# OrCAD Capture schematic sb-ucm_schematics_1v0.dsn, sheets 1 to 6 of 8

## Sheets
1 07. Ethernet, Camera & Headers: size C; title: SB-UCM    07. Ethernet, Camera & Headers; rev: 1.0; note: 8000076000; note: 17 HaYetsira Street; note: Yokneam Illit, Israel 2069208
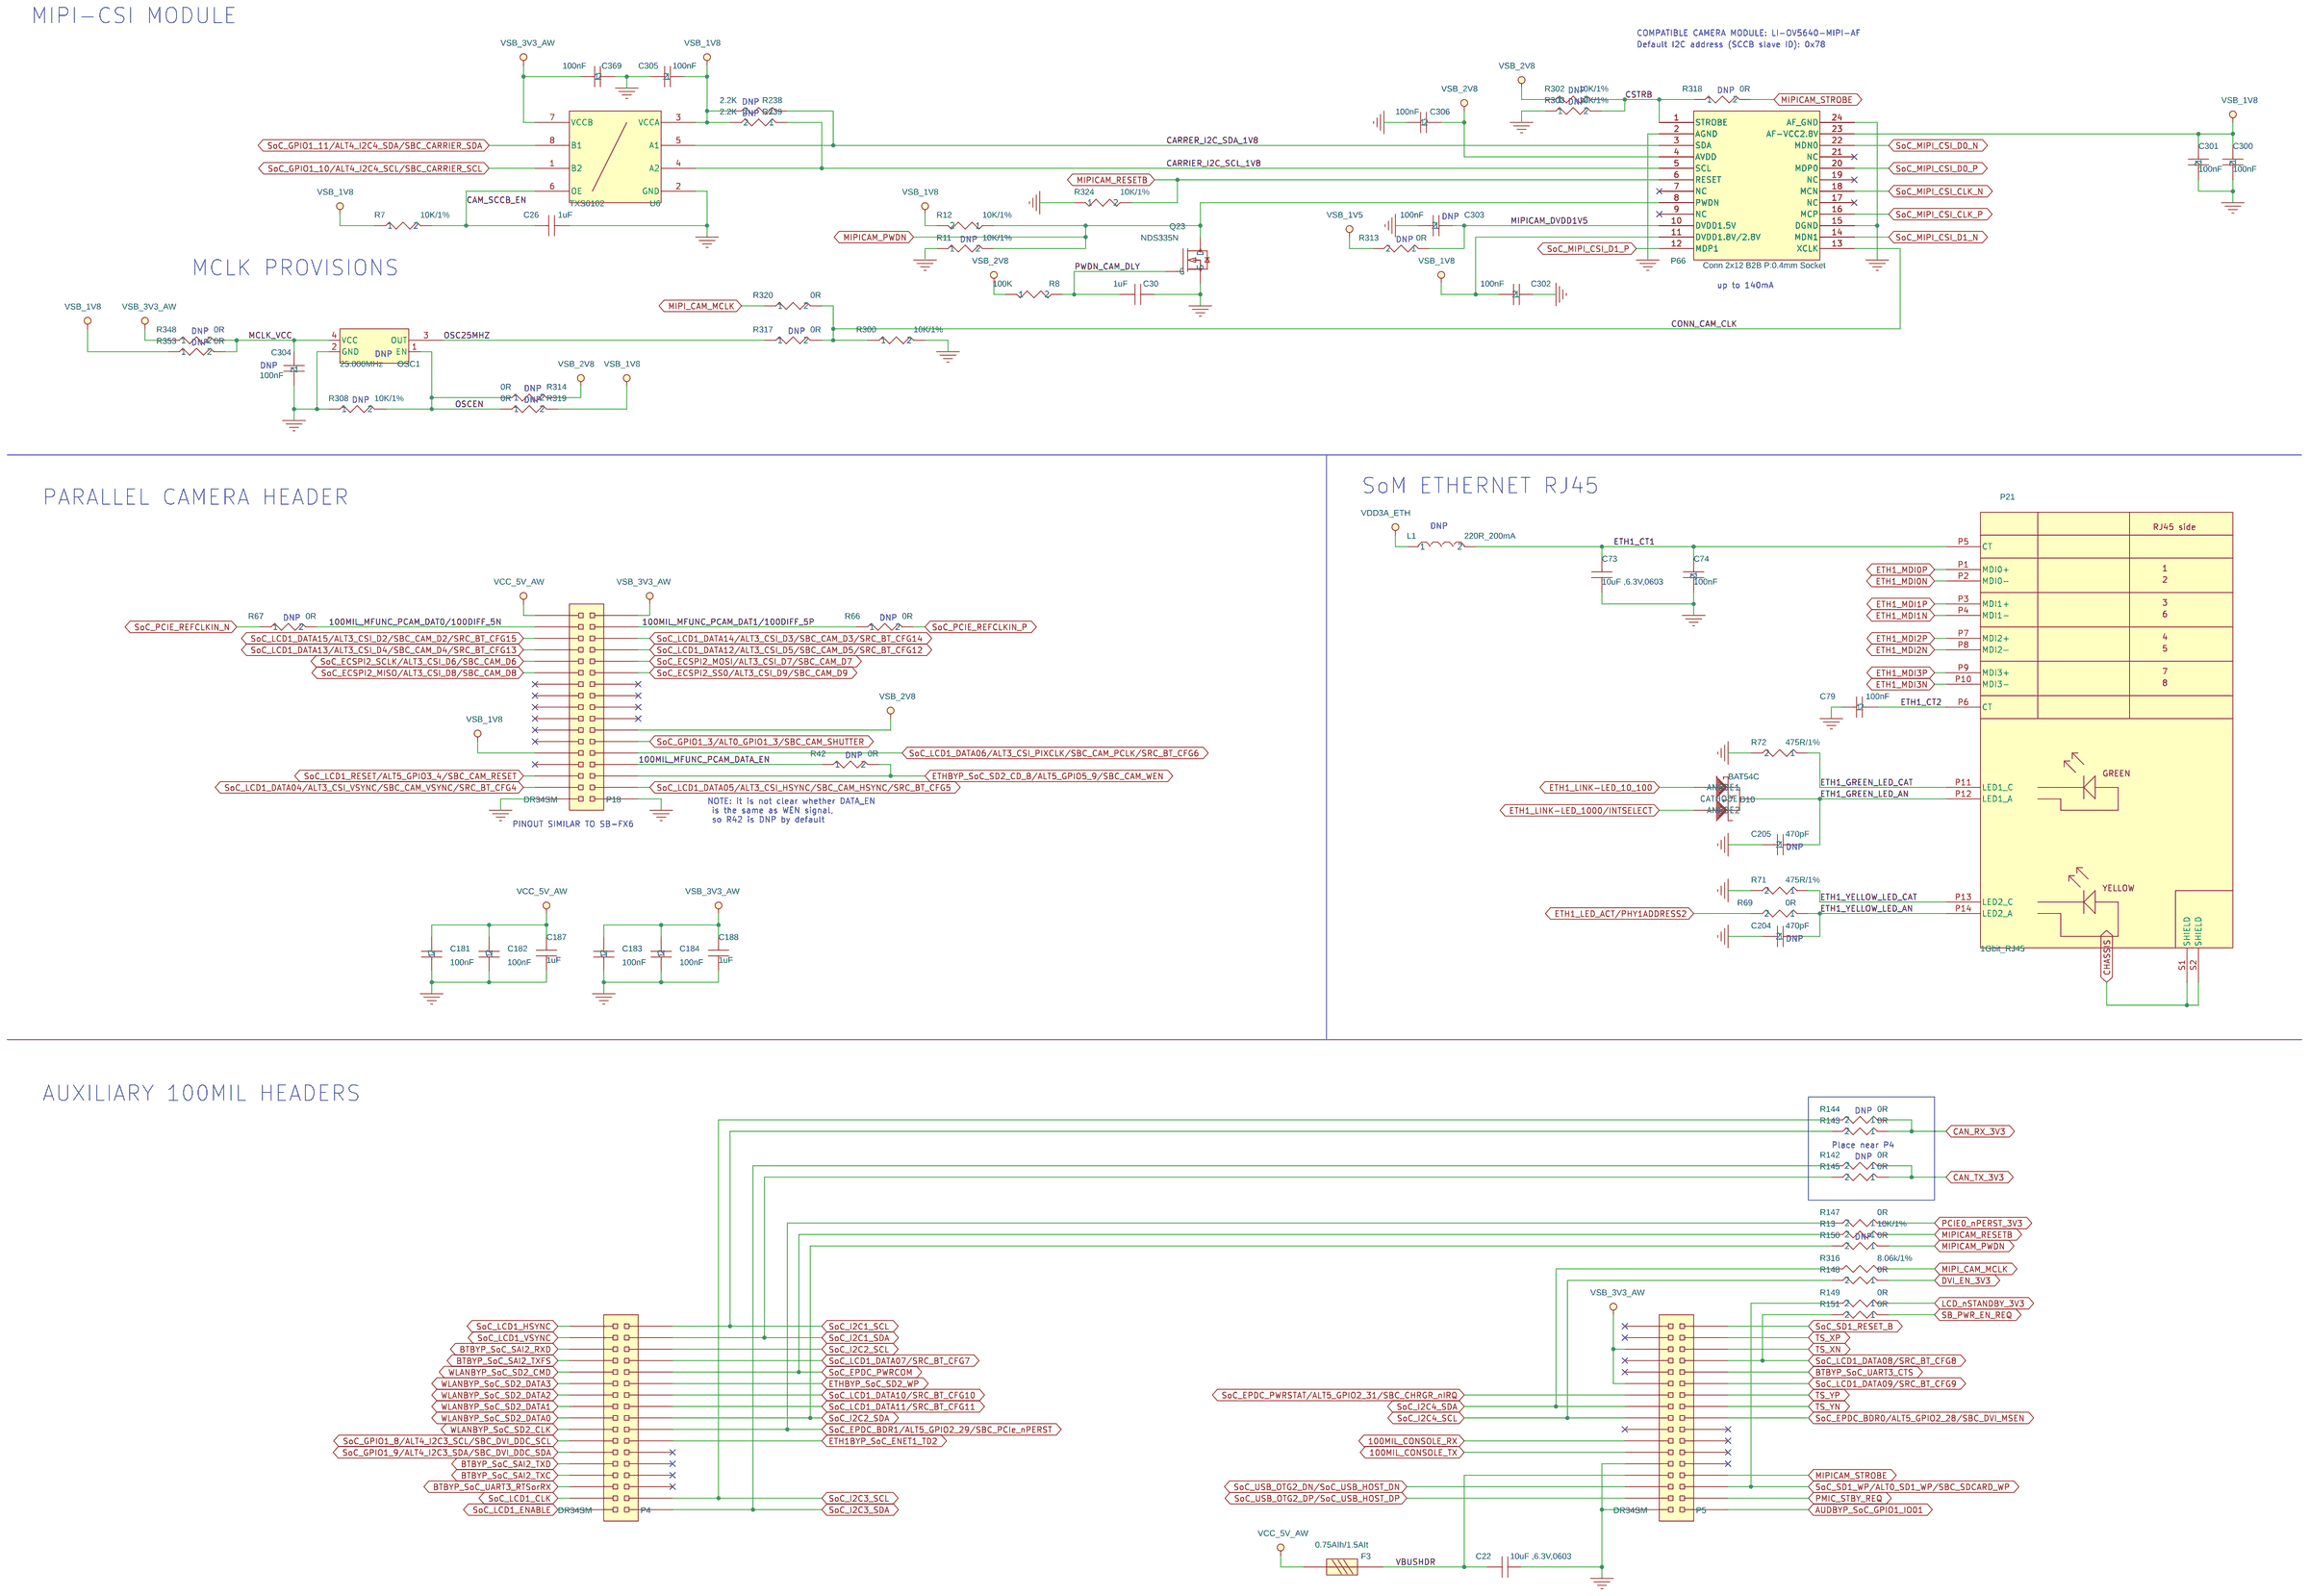
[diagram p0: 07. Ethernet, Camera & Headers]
2 02. Board Revision History: title: SB-UCM    02. Board Revision History
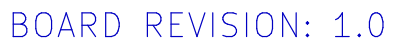
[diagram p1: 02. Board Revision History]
3 01. Index: size C; title: SB-UCM    01. Index
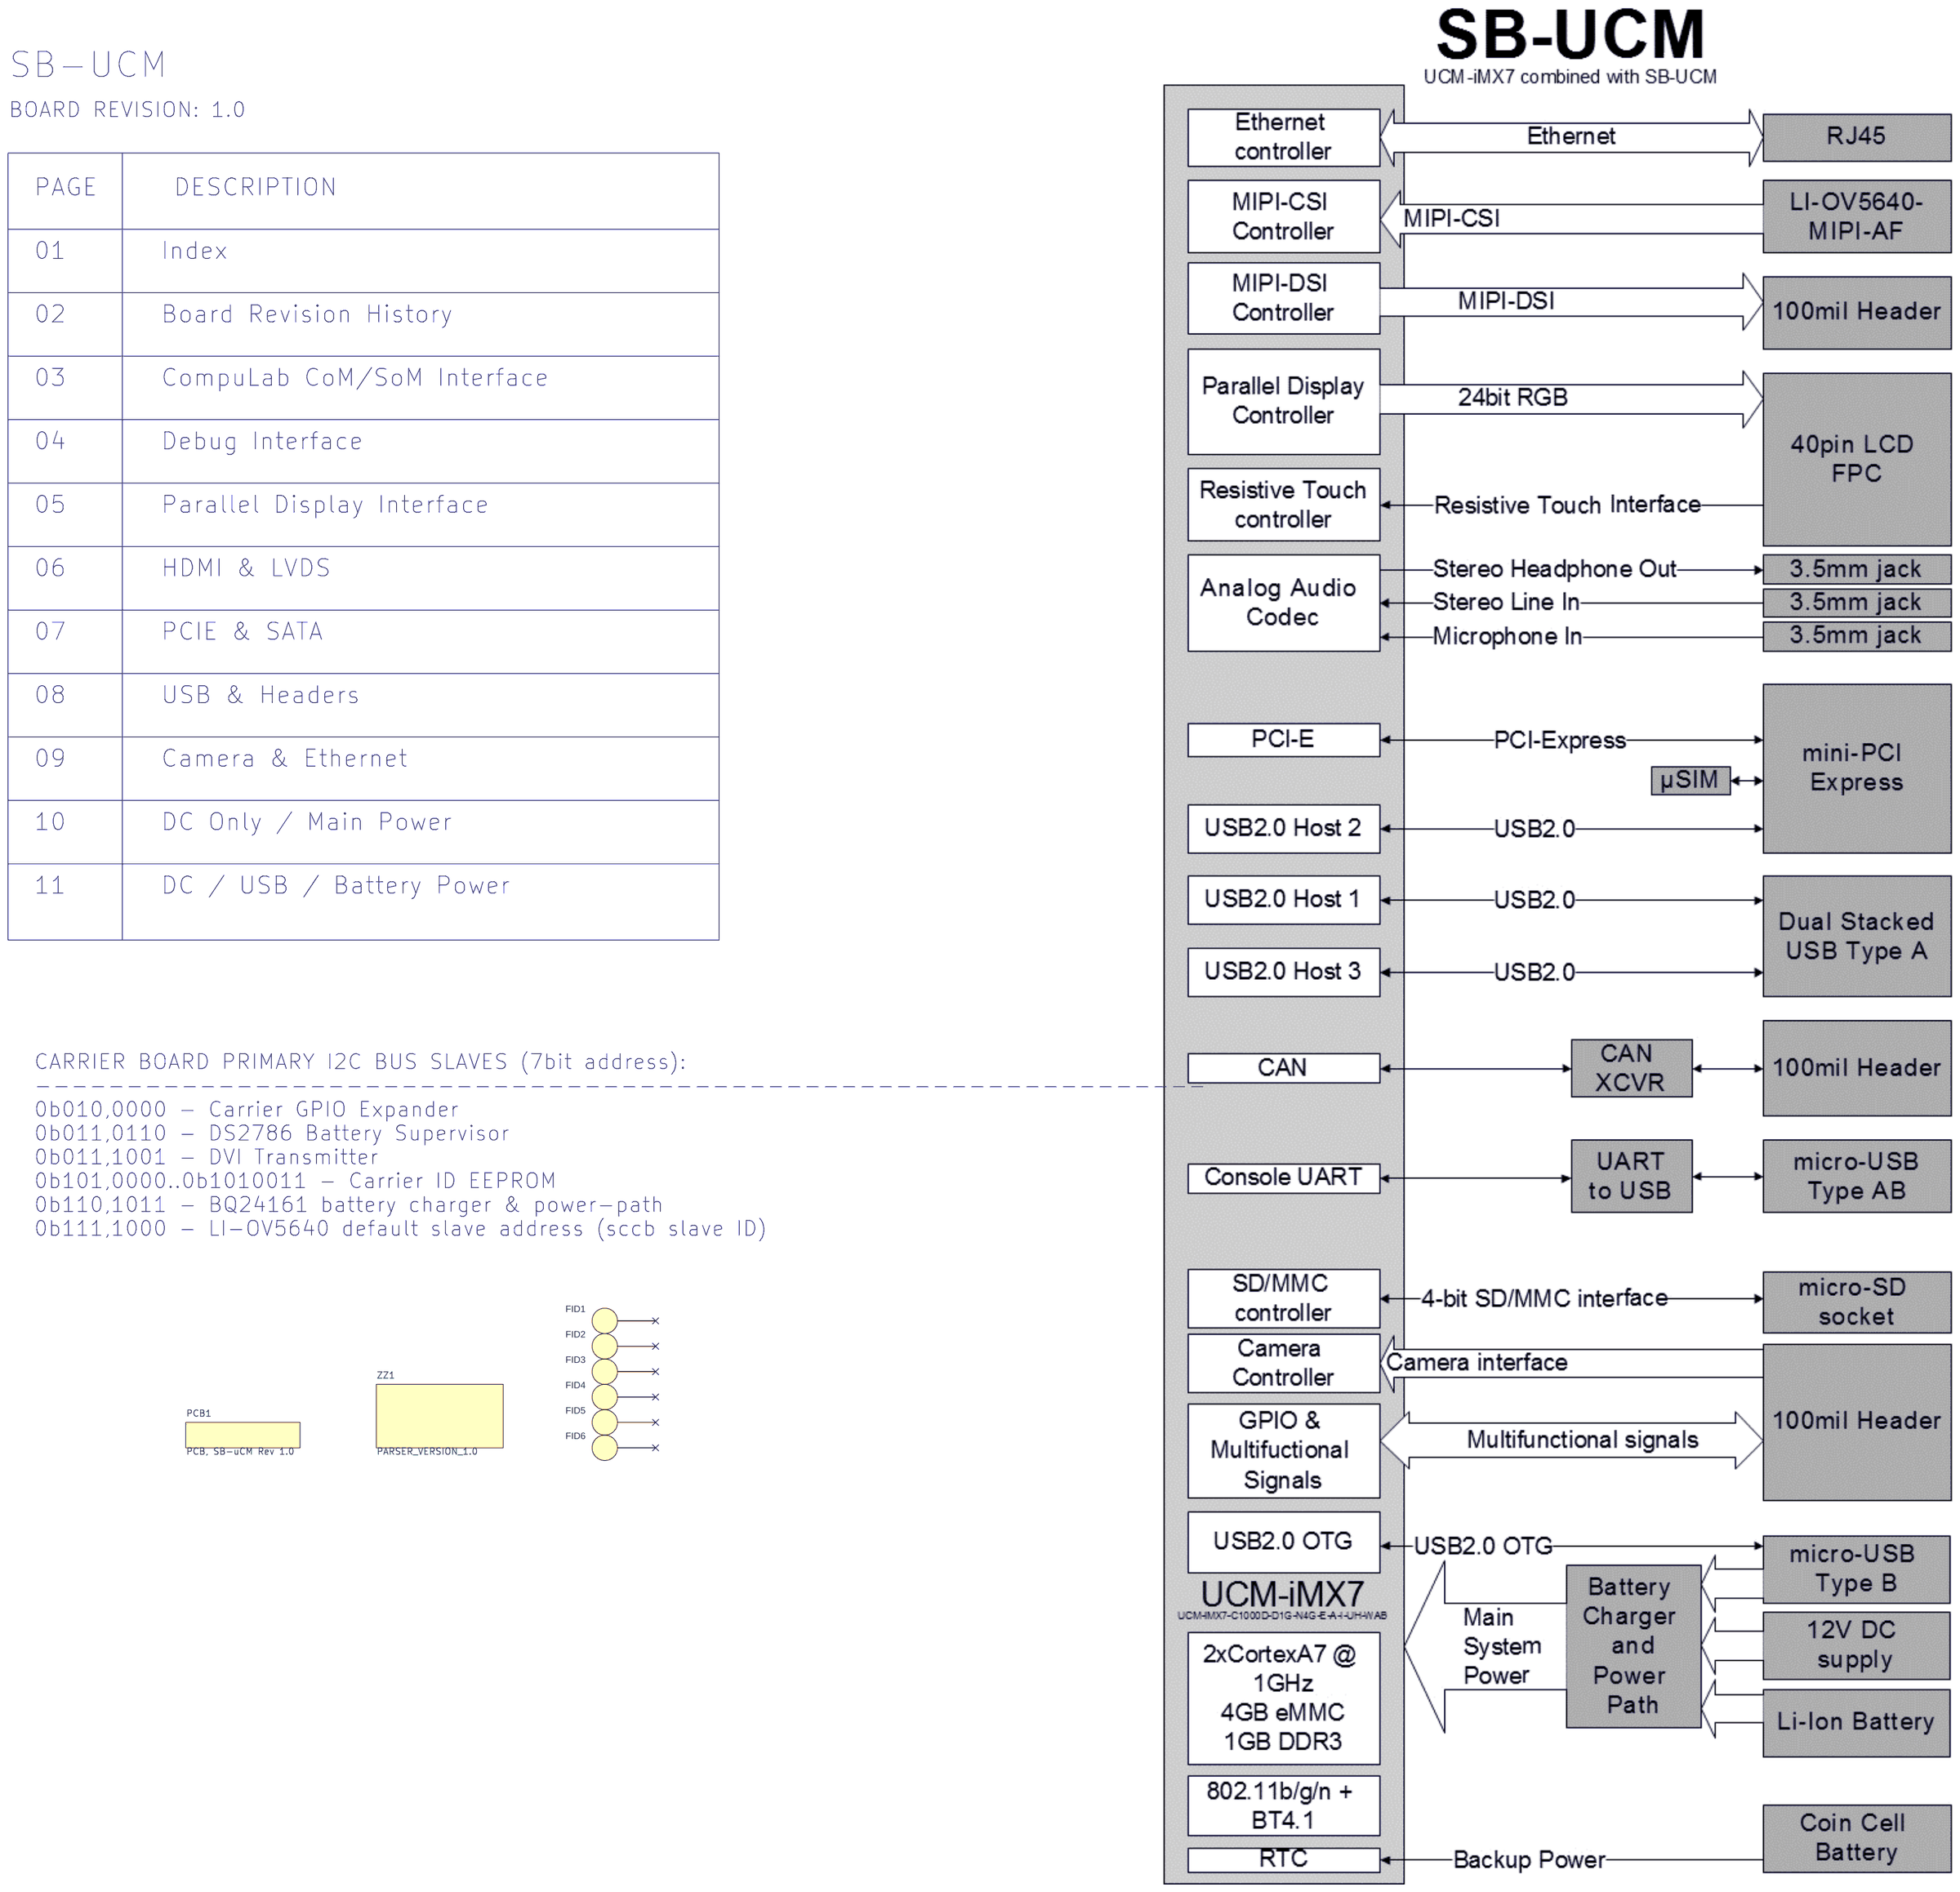
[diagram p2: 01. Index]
4 04. Console, CAN, SD, Buttons: size C; title: SB-UCM    04. Console, CAN, SD, Buttons
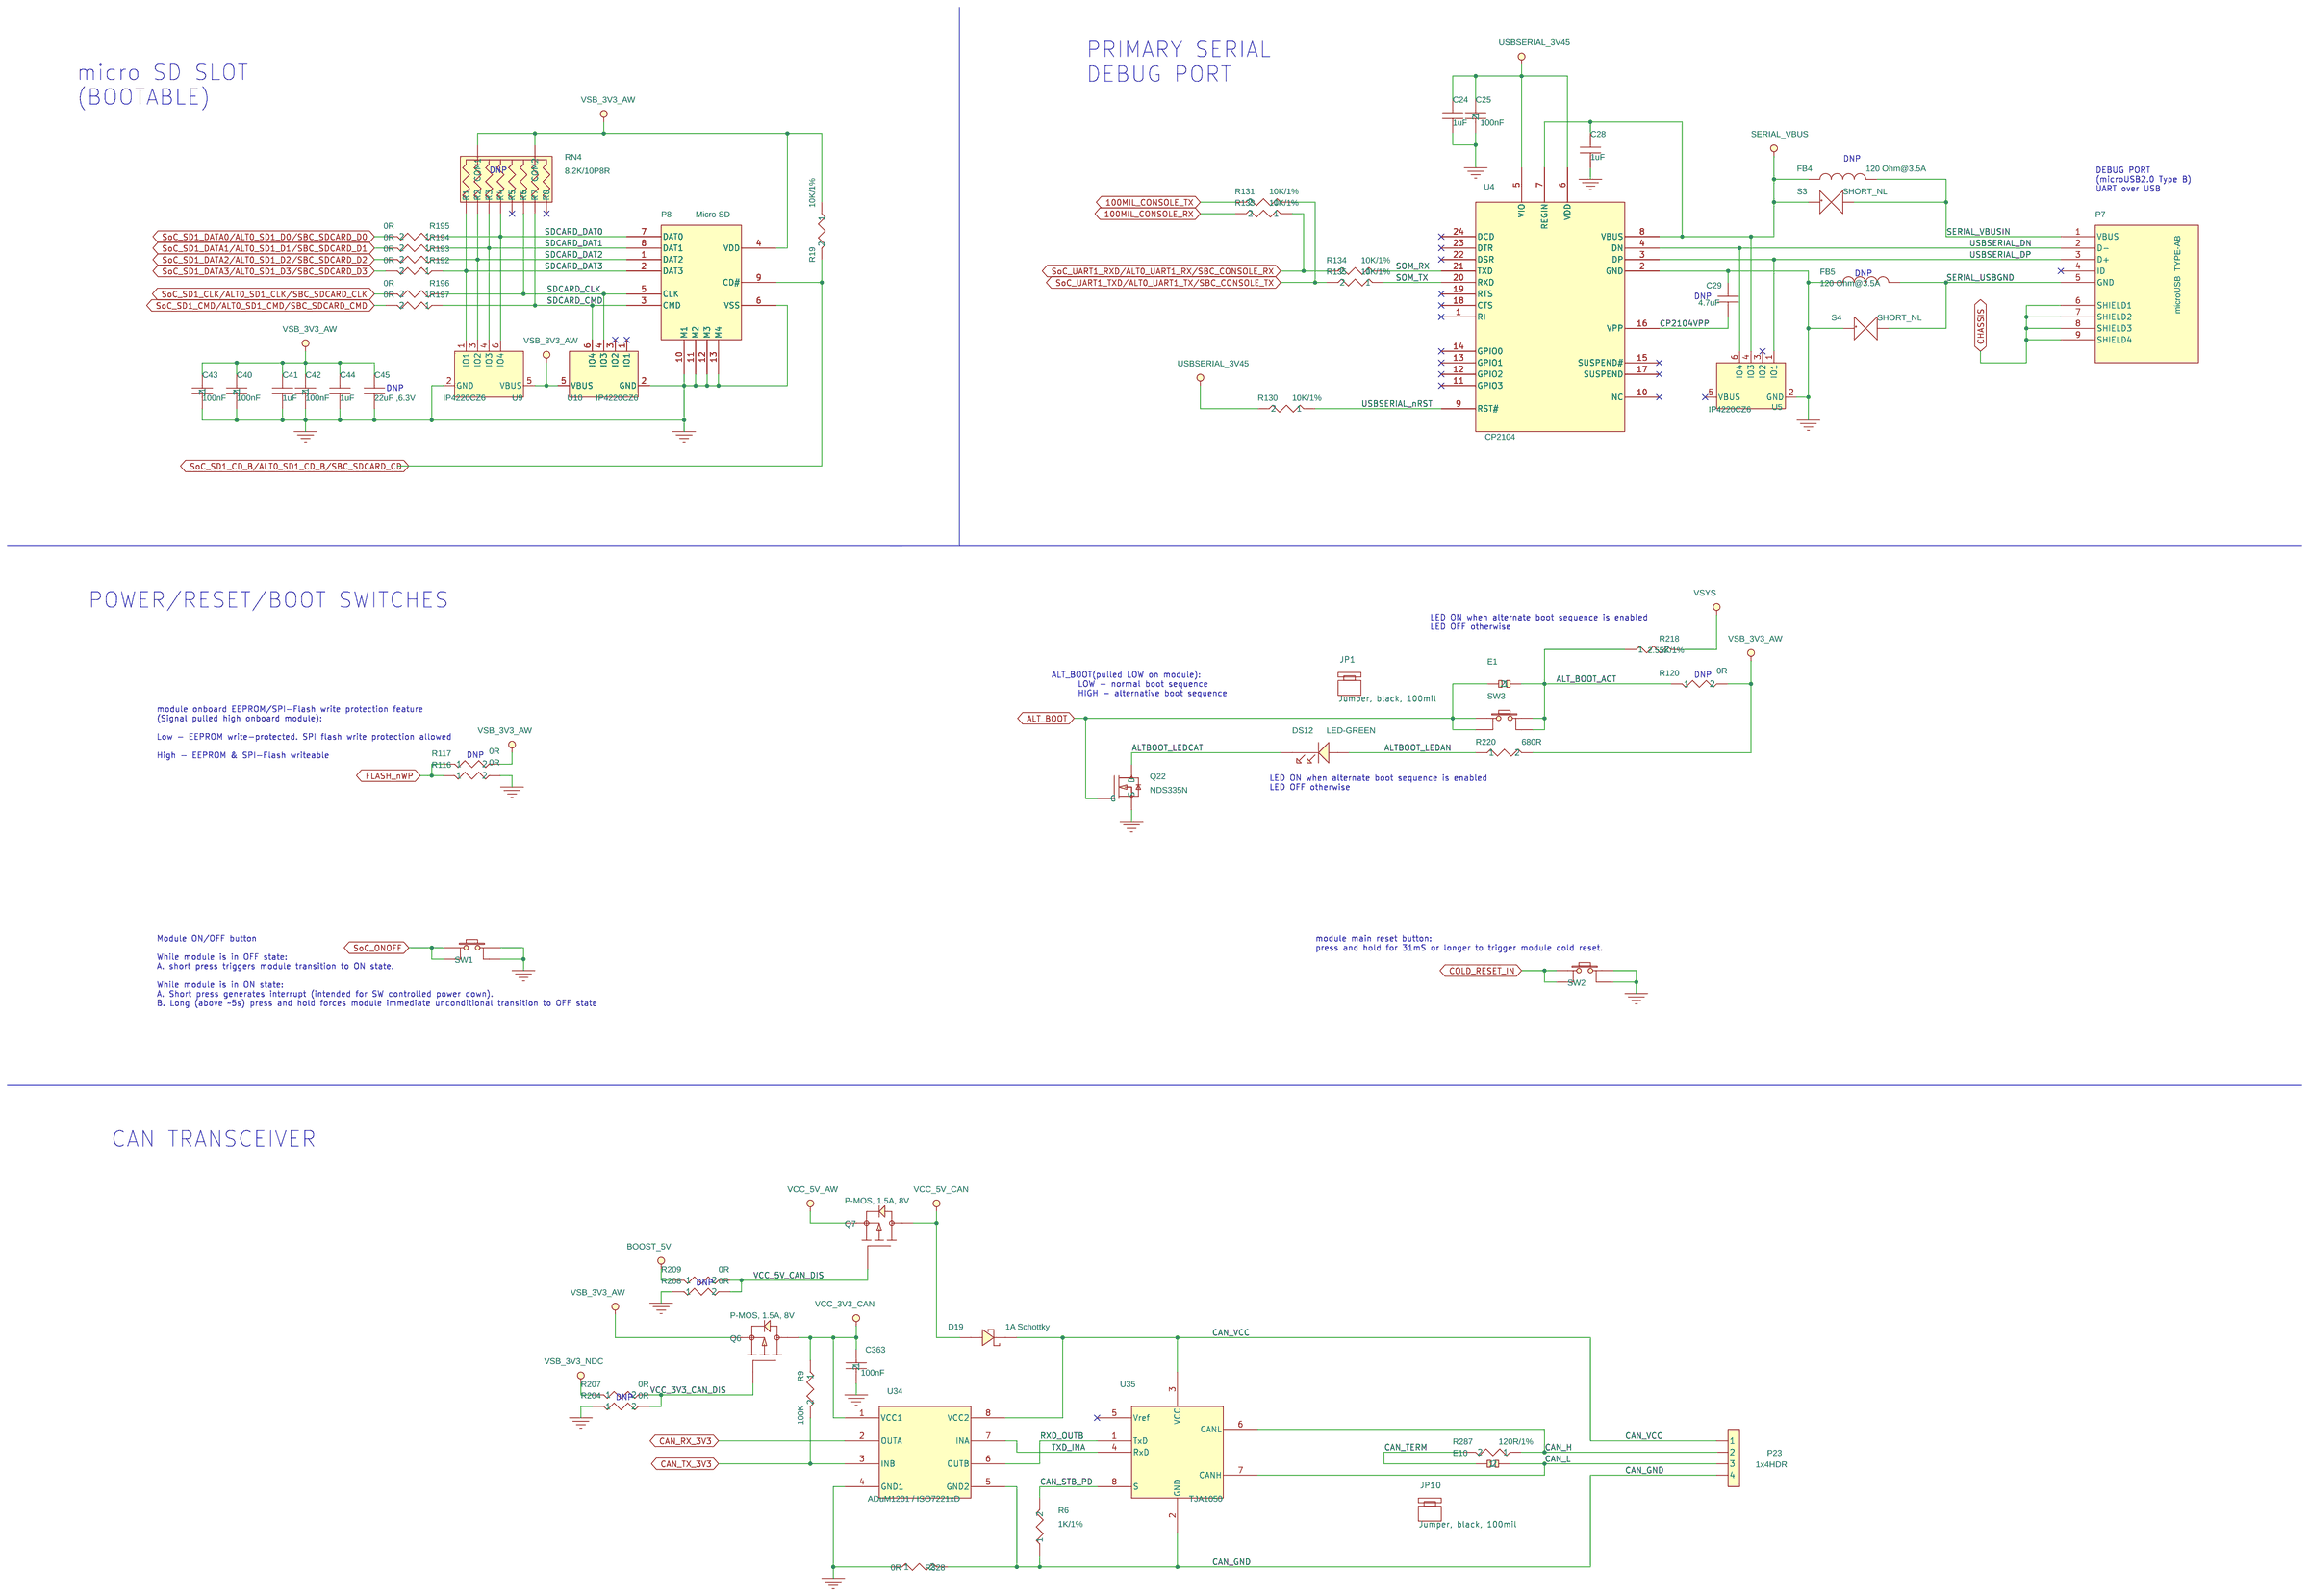
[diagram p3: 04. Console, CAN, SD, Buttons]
5 05. Display: size C; title: SB-UCM    05. Display
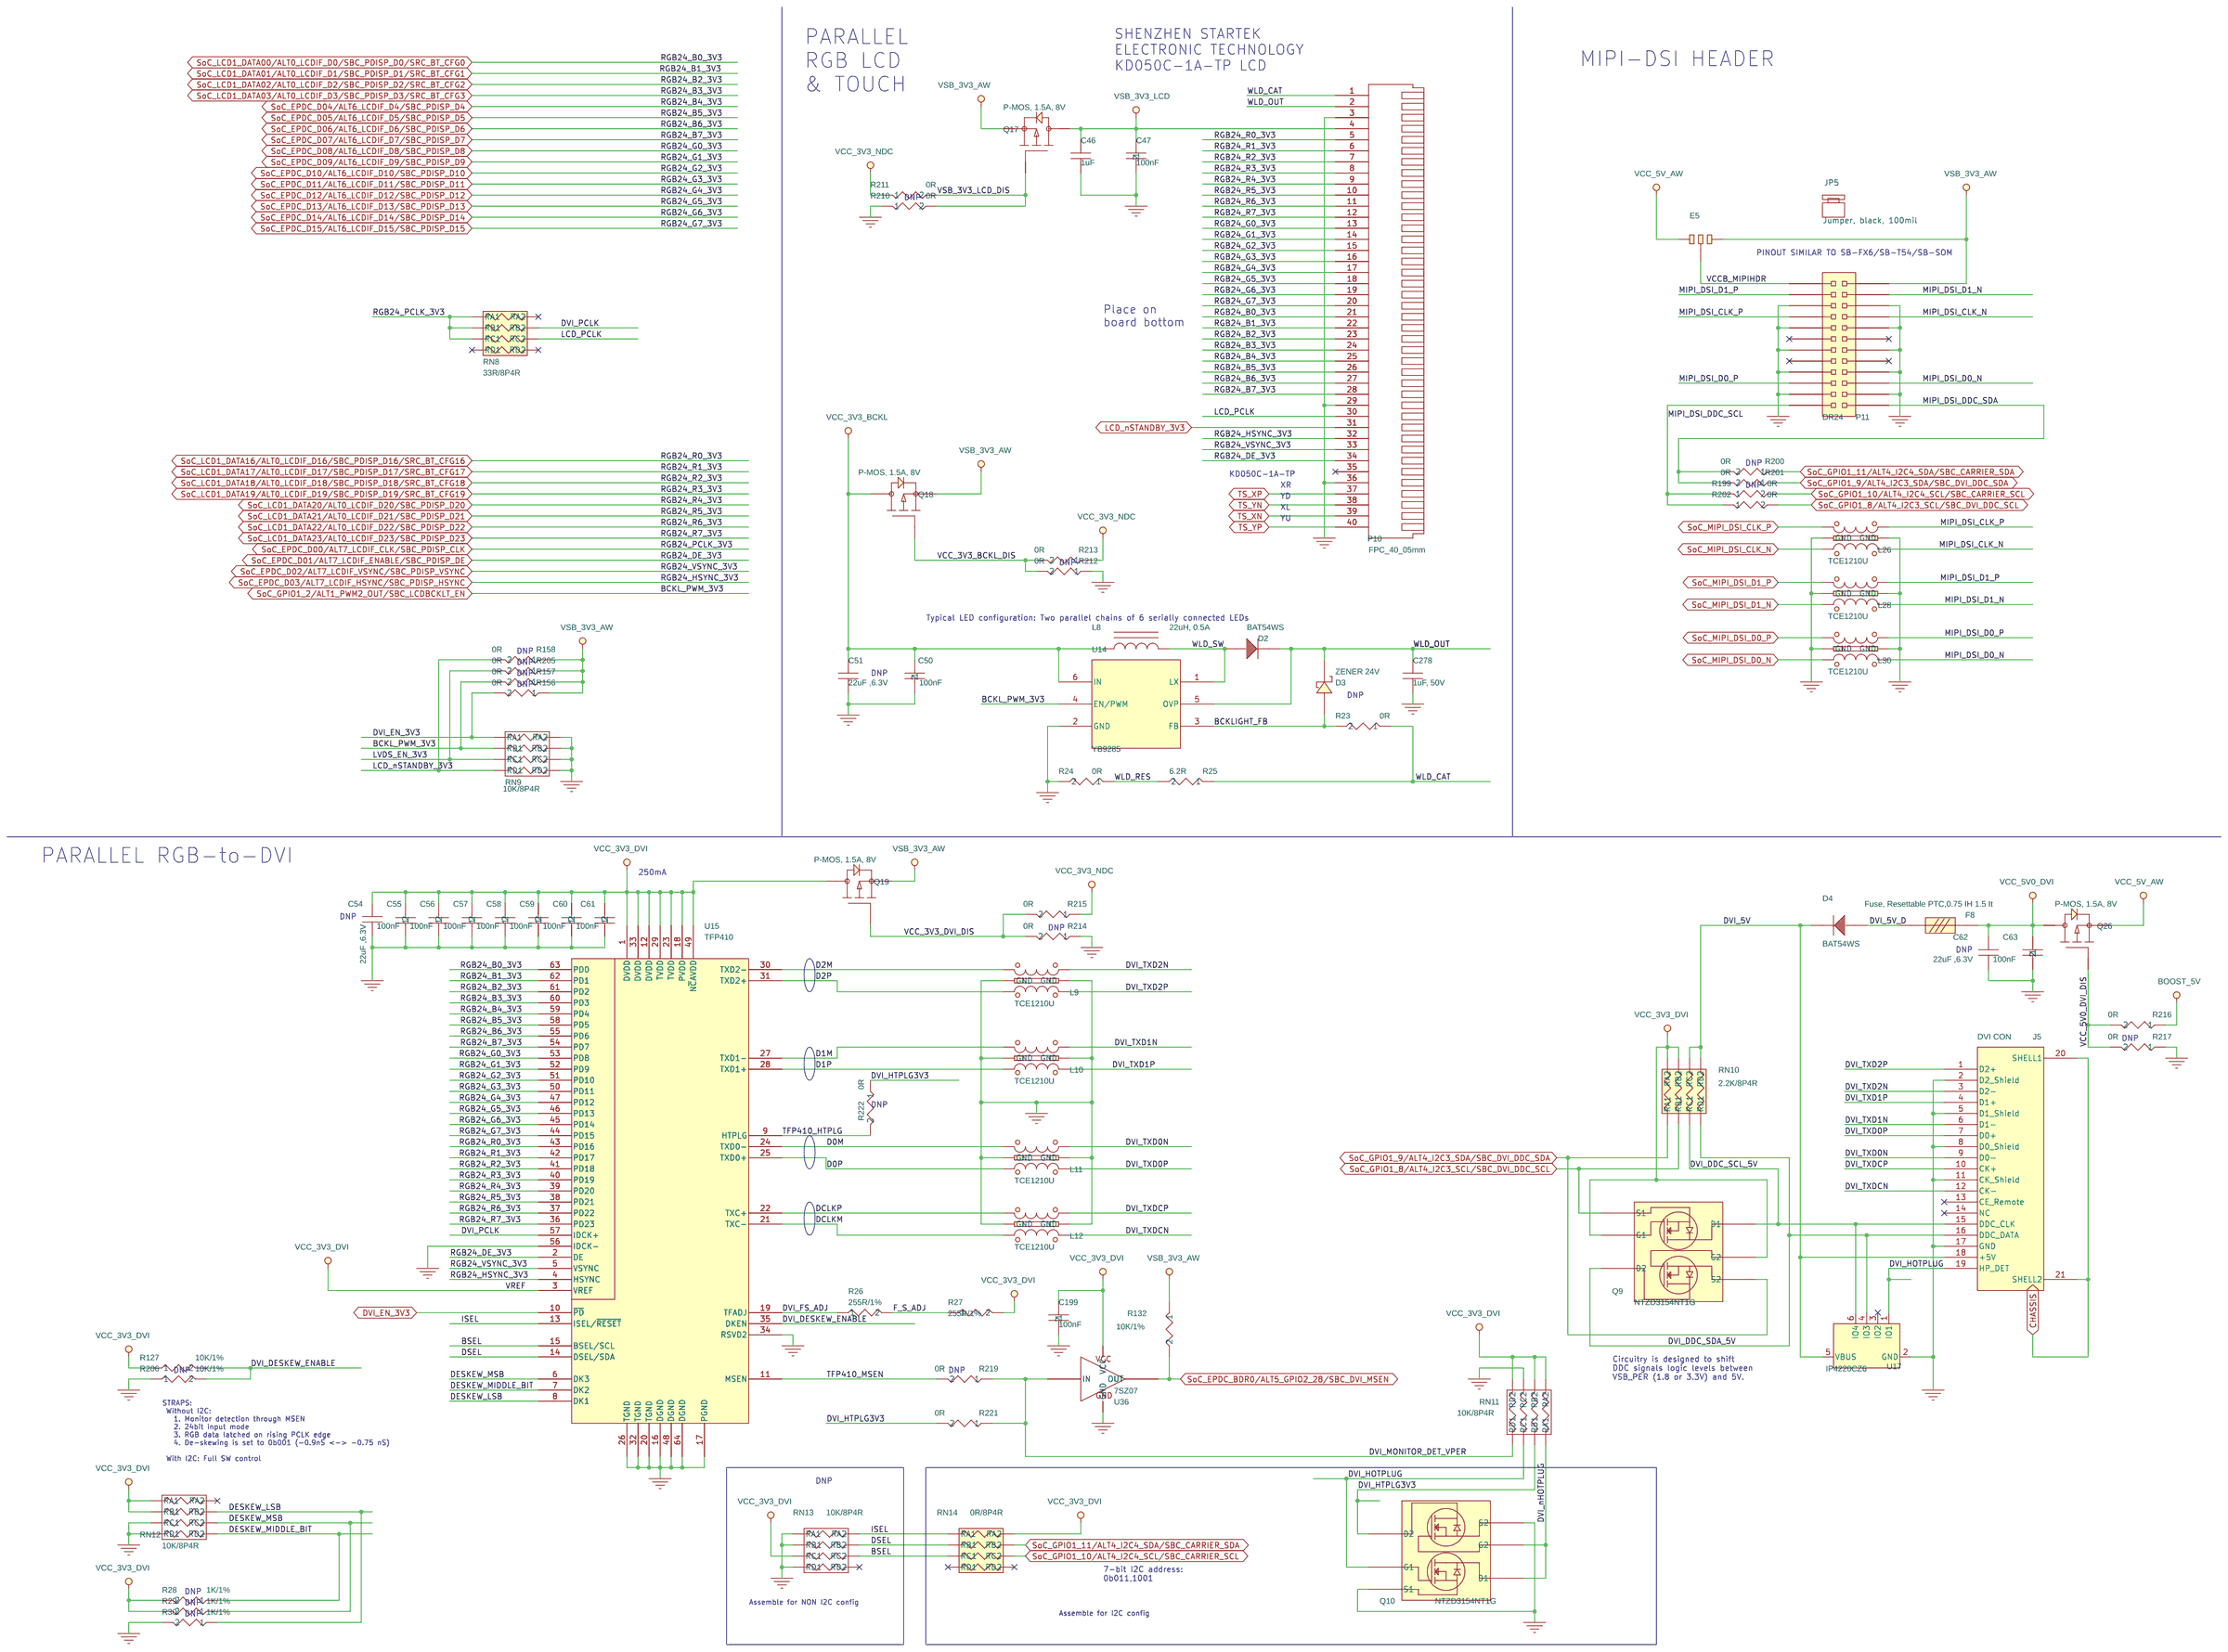
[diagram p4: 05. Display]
6 06. PCIE, USB & Misc.: size C; title: SB-UCM    06. PCIE, USB & Misc.
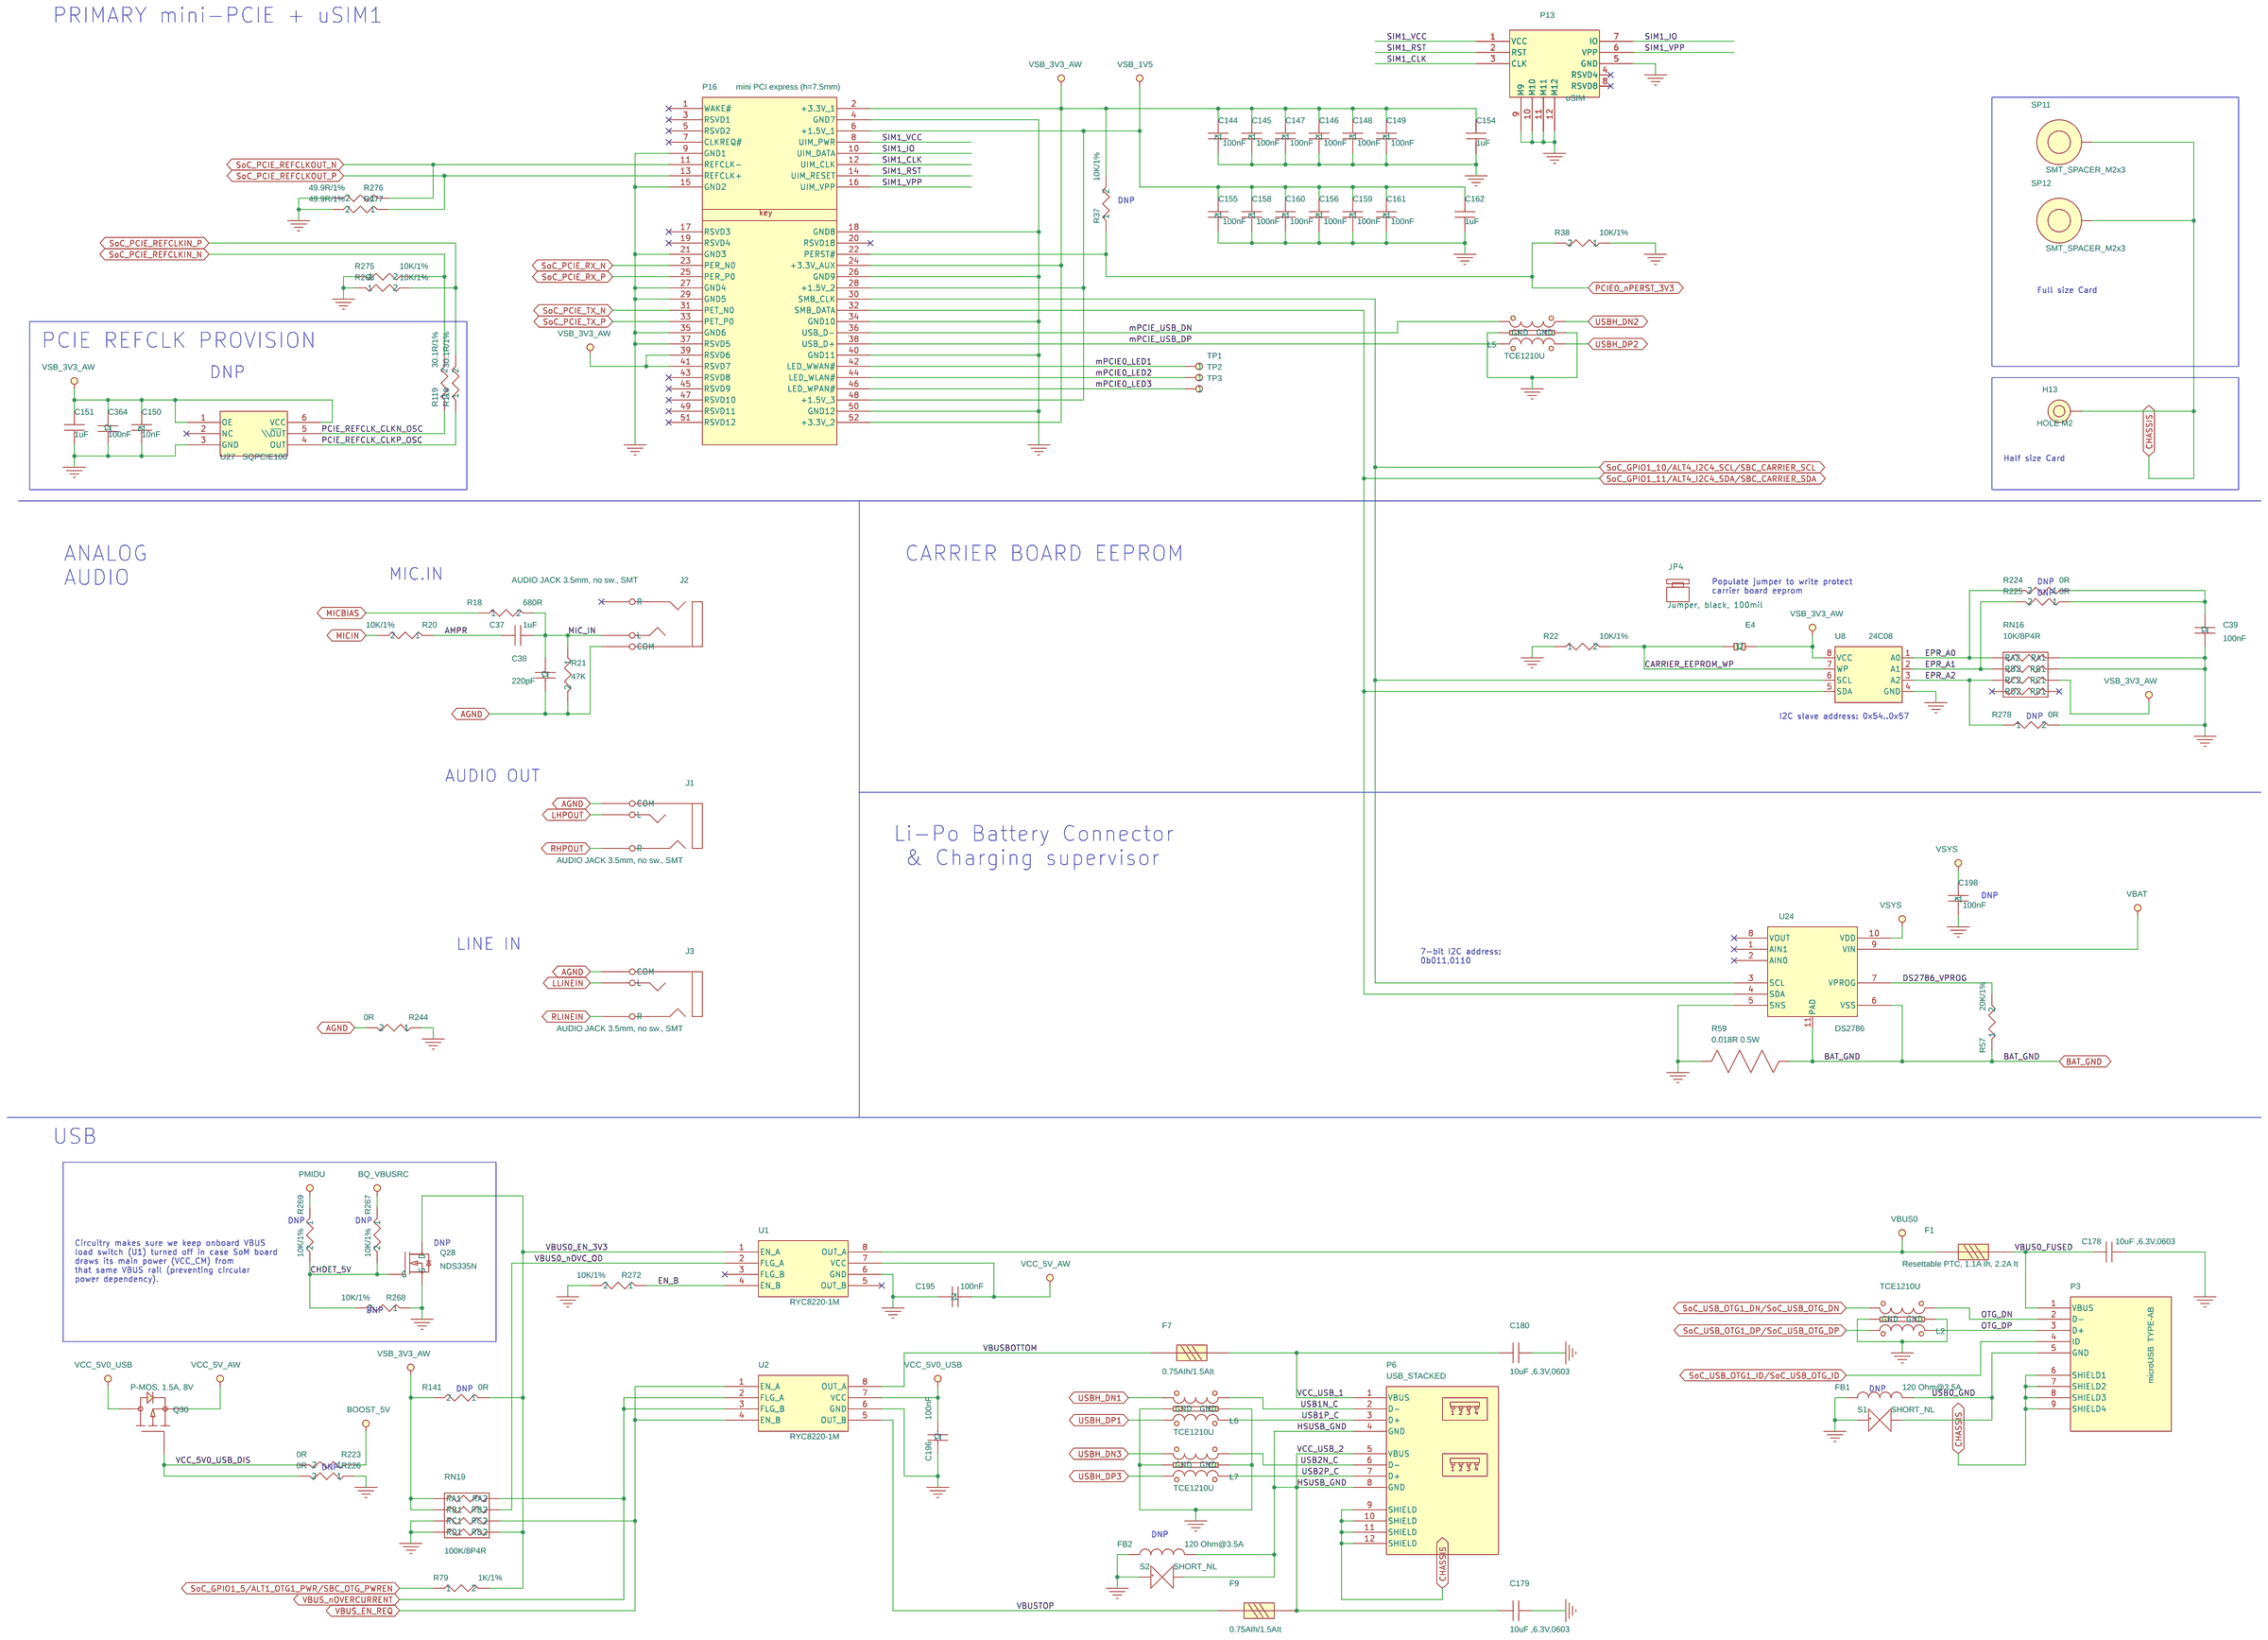
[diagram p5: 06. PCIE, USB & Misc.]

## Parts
sheet 01. Index
FID1  FIDUCIAL  [FIDUCIAL]
FID2  FIDUCIAL  [FIDUCIAL]
FID3  FIDUCIAL  [FIDUCIAL]
FID4  FIDUCIAL  [FIDUCIAL]
FID5  FIDUCIAL  [FIDUCIAL]
FID6  FIDUCIAL  [FIDUCIAL]
PCB1  PCB, SB-uCM Rev 1.0  [PCB]
ZZ1  PARSER_VERSION_1.0  [PCB]
sheet 04. Console, CAN, SD, Buttons
C24  1uF  [RC0402]
C25  100nF  [RC0402]
C28  1uF  [RC0402]
C29  4.7uF  [C0603-08]
C40  100nF  [RC0402]
C41  1uF  [RC0402]
C42  100nF  [RC0402]
C43  100nF  [RC0402]
C44  1uF  [RC0402]
C45  22uF ,6.3V  [RC0603]
C363  100nF  [RC0402]
D19  1A Schottky  [SOD-123]
DS12  LED-GREEN  [LED-1206]
E1  HDR1X2  [1X2THHDR]
E10  HDR1X2  [1X2THHDR]
FB4  120 Ohm@3.5A  [FB1206]
FB5  120 Ohm@3.5A  [FB1206]
JP1  Jumper, black, 100mil  [Shunt/Jumper]
JP10  Jumper, black, 100mil  [Shunt/Jumper]
P7  microUSB  TYPE-AB  [MICRO-USB-AB-RA-SM]
P8  Micro SD  [MicroSD-PP-RA-CD-SM]
P23  1x4HDR  [1X4THHDR]
Q6  P-MOS, 1.5A, 8V  [SOT23]
Q7  P-MOS, 1.5A, 8V  [SOT23]
Q22  NDS335N  [SOT23]
R6  1K/1%  [RC0402]
R9  100K  [RC0402]
R19  10K/1%  [RC0402]
R116  0R  [RC0402]
R117  0R  [RC0402]
R120  0R  [RC0402]
R130  10K/1%  [RC0402]
R131  10K/1%  [RC0402]
R133  10K/1%  [RC0402]
R134  10K/1%  [RC0402]
R135  10K/1%  [RC0402]
R192  0R  [RC0402]
R193  0R  [RC0402]
R194  0R  [RC0402]
R195  0R  [RC0402]
R196  0R  [RC0402]
R197  0R  [RC0402]
R204  0R  [RC0402]
R207  0R  [RC0402]
R208  0R  [RC0402]
R209  0R  [RC0402]
R218  2.55K/1%  [RC0402]
R220  680R  [RC0402]
R287  120R/1%  [RC0603]
R328  0R  [RC0402]
RN4  8.2K/10P8R  [RESNET10P1206]
S3  SHORT_NL  [JUMPER-VIA_1]
S4  SHORT_NL  [JUMPER-VIA_1]
SW1  PushB  [TACTSW6x6SM]
SW2  PushB  [TACTSW6x6SM]
SW3  PushB  [TACTSW6x6SM]
U4  CP2104  [MO-220VGGD-8]
U5  IP4220CZ6  [SOT23-6L-H1]
U9  IP4220CZ6  [SOT23-6L-H1]
U10  IP4220CZ6  [SOT23-6L-H1]
U34  ADuM1201 / ISO7221xD  [SO-8-150]
U35  TJA1050  [SO-8-150]
sheet 05. Display
C46  1uF  [RC0402]
C47  100nF  [RC0402]
C50  100nF  [RC0402]
C51  22uF ,6.3V  [RC0603]
C54  22uF ,6.3V  [RC0603]
C55  100nF  [RC0402]
C56  100nF  [RC0402]
C57  100nF  [RC0402]
C58  100nF  [RC0402]
C59  100nF  [RC0402]
C60  100nF  [RC0402]
C61  100nF  [RC0402]
C62  22uF ,6.3V  [RC0603]
C63  100nF  [RC0402]
C199  100nF  [RC0402]
C278  1uF, 50V  [RC0603]
D2  BAT54WS  [SOD-323]
D3  ZENER 24V  [SOD-123]
D4  BAT54WS  [SOD-323]
E5  JP3  [1X3THHDR]
F8  Fuse, Resettable PTC,0.75 IH 1.5 It  [FUSE-1206]
J5  DVI CON  [HDMI-A19-RASM]
JP5  Jumper, black, 100mil  [Shunt/Jumper]
L8  22uH, 0.5A  [IND4x4_5x3_2S]
L9  TCE1210U  [EMI1012-ESD]
L10  TCE1210U  [EMI1012-ESD]
L11  TCE1210U  [EMI1012-ESD]
L12  TCE1210U  [EMI1012-ESD]
L26  TCE1210U  [EMI1012-ESD]
L28  TCE1210U  [EMI1012-ESD]
L30  TCE1210U  [EMI1012-ESD]
P10  FPC_40_05mm  [FPC05SM40-1]
P11  DR24  [2X12THHDR]
Q9  NTZD3154NT1G  [SOT-563-6]
Q10  NTZD3154NT1G  [SOT-563-6]
Q17  P-MOS, 1.5A, 8V  [SOT23]
Q18  P-MOS, 1.5A, 8V  [SOT23]
Q19  P-MOS, 1.5A, 8V  [SOT23]
Q26  P-MOS, 1.5A, 8V  [SOT23]
R23  0R  [RC0402]
R24  0R  [RC0402]
R25  6.2R  [RC0402]
R26  255R/1%  [RC0402]
R27  255R/1%  [RC0402]
R28  1K/1%  [RC0402]
R29  1K/1%  [RC0402]
R30  1K/1%  [RC0402]
R127  10K/1%  [RC0402]
R132  10K/1%  [RC0402]
R156  0R  [RC0402]
R157  0R  [RC0402]
R158  0R  [RC0402]
R199  0R  [RC0402]
R200  0R  [RC0402]
R201  0R  [RC0402]
R202  0R  [RC0402]
R205  0R  [RC0402]
R206  10K/1%  [RC0402]
R210  0R  [RC0402]
R211  0R  [RC0402]
R212  0R  [RC0402]
R213  0R  [RC0402]
R214  0R  [RC0402]
R215  0R  [RC0402]
R216  0R  [RC0402]
R217  0R  [RC0402]
R219  0R  [RC0402]
R221  0R  [RC0402]
R222  0R  [RC0402]
RN8  33R/8P4R  [RESNET8P0805]
RN9  10K/8P4R  [RESNET8P0805]
RN10  2.2K/8P4R  [RESNET8P0805]
RN11  10K/8P4R  [RESNET8P0805]
RN12  10K/8P4R  [RESNET8P0805]
RN13  10K/8P4R  [RESNET8P0805]
RN14  0R/8P4R  [RESNET8P0805]
U14  YB9285  [SOT23-6L]
U15  TFP410  [TQFP-64]
U17  IP4220CZ6  [SOT23-6L-H1]
U36  7SZ07  [SC70]
sheet 06. PCIE, USB & Misc.
C37  1uF  [RC0402]
C38  220pF  [RC0603]
C39  100nF  [RC0402]
C144  100nF  [RC0402]
C145  100nF  [RC0402]
C146  100nF  [RC0402]
C147  100nF  [RC0402]
C148  100nF  [RC0402]
C149  100nF  [RC0402]
C150  10nF  [RC0402]
C151  1uF  [RC0402]
C154  1uF  [RC0402]
C155  100nF  [RC0402]
C156  100nF  [RC0402]
C158  100nF  [RC0402]
C159  100nF  [RC0402]
C160  100nF  [RC0402]
C161  100nF  [RC0402]
C162  1uF  [RC0402]
C178  10uF ,6.3V,0603  [C0603-08]
C179  10uF ,6.3V,0603  [C0603-08]
C180  10uF ,6.3V,0603  [C0603-08]
C195  100nF  [RC0402]
C196  100nF  [RC0402]
C198  100nF  [RC0402]
C364  100nF  [RC0402]
E4  HDR1X2  [1X2THHDR]
F1  Resettable PTC, 1.1A Ih, 2.2A It  [FUSE-1206]
F7  0.75AIh/1.5AIt  [FUSE-1206]
F9  0.75AIh/1.5AIt  [FUSE-1206]
FB1  120 Ohm@3.5A  [FB1206]
FB2  120 Ohm@3.5A  [FB1206]
H13  HOLE M2  [M2PAD]
J1  AUDIO JACK 3.5mm, no sw., SMT  [AJ35-3P-SM]
J2  AUDIO JACK 3.5mm, no sw., SMT  [AJ35-3P-SM]
J3  AUDIO JACK 3.5mm, no sw., SMT  [AJ35-3P-SM]
JP4  Jumper, black, 100mil  [Shunt/Jumper]
L2  TCE1210U  [EMI1012-ESD]
L5  TCE1210U  [EMI1012-ESD]
L6  TCE1210U  [EMI1012-ESD]
L7  TCE1210U  [EMI1012-ESD]
P3  microUSB  TYPE-AB  [MICRO-USB-AB-RA-SM]
P6  USB_STACKED  [USB-2XA-TH]
P13  uSIM  [SKT-MicroSIM6-SM]
P16  mini PCI express (h=7.5mm)  [MINIPCIE-4]
Q28  NDS335N  [SOT23]
Q30  P-MOS, 1.5A, 8V  [SOT23]
R18  680R  [RC0402]
R20  10K/1%  [RC0402]
R21  47K  [RC0402]
R22  10K/1%  [RC0402]
R37  10K/1%  [RC0402]
R38  10K/1%  [RC0402]
R57  20K/1%  [RC0402]
R59  0.018R 0.5W  [R2010]
R79  1K/1%  [RC0402]
R118  30.1R/1%  [RC0402]
R119  30.1R/1%  [RC0402]
R141  0R  [RC0402]
R223  0R  [RC0402]
R224  0R  [RC0402]
R225  0R  [RC0402]
R226  0R  [RC0402]
R244  0R  [RC0402]
R265  10K/1%  [RC0402]
R267  10K/1%  [RC0402]
R268  10K/1%  [RC0402]
R269  10K/1%  [RC0402]
R272  10K/1%  [RC0402]
R275  10K/1%  [RC0402]
R276  49.9R/1%  [RC0402]
R277  49.9R/1%  [RC0402]
R278  0R  [RC0402]
RN16  10K/8P4R  [RESNET8P0805]
RN19  100K/8P4R  [RESNET8P0805]
S1  SHORT_NL  [JUMPER-VIA_1]
S2  SHORT_NL  [JUMPER-VIA_1]
SP11  SMT_SPACER_M2x3  [SpacerM2H4SM]
SP12  SMT_SPACER_M2x3  [SpacerM2H4SM]
TP1  TESTPOINT  [TESTPOINT]
TP2  TESTPOINT  [TESTPOINT]
TP3  TESTPOINT  [TESTPOINT]
U1  RYC8220-1M  [SO-8-150]
U2  RYC8220-1M  [SO-8-150]
U8  24C08  [MO-229VCED-2]
U24  DS2786  [DFN3x3-10]
U27  SQPCIE100  [OSC5x3.2-6]
sheet 07. Ethernet, Camera & Headers
C22  10uF ,6.3V,0603  [C0603-08]
C26  1uF  [RC0402]
C30  1uF  [RC0402]
C73  10uF ,6.3V,0603  [C0603-08]
C74  100nF  [RC0402]
C79  100nF  [RC0402]
C181  100nF  [RC0402]
C182  100nF  [RC0402]
C183  100nF  [RC0402]
C184  100nF  [RC0402]
C187  1uF  [RC0402]
C188  1uF  [RC0402]
C204  470pF  [RC0603]
C205  470pF  [RC0603]
C300  100nF  [RC0402]
C301  100nF  [RC0402]
C302  100nF  [RC0402]
C303  100nF  [RC0402]
C304  100nF  [RC0402]
C305  100nF  [RC0402]
C306  100nF  [RC0402]
C369  100nF  [RC0402]
D10  BAT54C  [SOT23]
F3  0.75AIh/1.5AIt  [FUSE-1206]
L1  220R_200mA  [FB0402]
OSC1  25.000MHz  [OSC3225]
P4  DR34SM  [2X17SMHDR]
P5  DR34SM  [2X17SMHDR]
P18  DR34SM  [2X17SMHDR]
P21  1Gbit_RJ45  [RJTR1GRATH]
P66  Conn 2x12 B2B P:0.4mm Socket  [B2B04M2X12R]
Q23  NDS335N  [SOT23]
R7  10K/1%  [RC0402]
R8  100K  [RC0402]
R11  10K/1%  [RC0402]
R12  10K/1%  [RC0402]
R13  10K/1%  [RC0402]
R42  0R  [RC0402]
R66  0R  [RC0402]
R67  0R  [RC0402]
R69  0R  [RC0402]
R71  475R/1%  [RC0402]
R72  475R/1%  [RC0402]
R142  0R  [RC0402]
R143  0R  [RC0402]
R144  0R  [RC0402]
R145  0R  [RC0402]
R147  0R  [RC0402]
R148  0R  [RC0402]
R149  0R  [RC0402]
R150  0R  [RC0402]
R151  0R  [RC0402]
R238  2.2K  [RC0402]
R239  2.2K  [RC0402]
R300  10K/1%  [RC0402]
R302  10K/1%  [RC0402]
R303  10K/1%  [RC0402]
R308  10K/1%  [RC0402]
R313  0R  [RC0402]
R314  0R  [RC0402]
R316  8.06k/1%  [RC0402]
R317  0R  [RC0402]
R318  0R  [RC0402]
R319  0R  [RC0402]
R320  0R  [RC0402]
R324  10K/1%  [RC0402]
R348  0R  [RC0402]
R353  0R  [RC0402]
U6  TXS0102  [MO-187DA-8]

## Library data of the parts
FID1-FID6 = TESTPOINT_2: CLABCONF0: DNP
PCB1 = PCB,_EM-X270_Rev_1_0.1: CLABCONF0: = SB-UCM; P/N: 188C03010
ZZ1 = PARSER_VERSION_1_1.0
C24 C26 C28 C30 C37 C41 C44 C46 C154 C162 C187 C188 = 1uF,X5R,6.3V,0402: CLABCONF0: = SB-UCM
C25 C59 C198 = 100nF,_10V,_X7R,_10%,_0402: CLABCONF0: = SB-UCM
C29 = 4.7uF,_6.3V,_X5R,_20%,_0603: CLABCONF0: DNP
C40 C145 C301 = 100nF,_10V,_X7R,_10%,_0402_3: CLABCONF0: = SB-UCM
C42 C50 C144 = 100nF,_10V,_X7R,_10%,_0402_2: CLABCONF0: = SB-UCM
C43 C60 C196 C300 = 100nF,_10V,_X7R,_10%,_0402_1: CLABCONF0: = SB-UCM
C45 C54 = 22uF,6.3V,X5R: CLABCONF0: DNP; P/N: 151B22610S
C363 = 100nF,_10V,_X7R,_10%,_0402_4: CLABCONF0: = SB-UCM; Group: CAN
D19 = 1A_Schottky_Barrier_Rectifier: CLABCONF0: = SB-UCM
DS12 = LED-GREEN_1206_3: CLABCONF0: = SB-UCM
E1 E4 = HDR_1x2_100MIL_TH_JUMPER: CLABCONF0: = SB-UCM
E10 = HDR_1x2_100MIL_TH_JUMPER_1: CLABCONF0: = SB-UCM
FB1 FB4 = Ferrite_bead_,_120_Ohm@3A: CLABCONF0: DNP
FB2 FB5 = Ferrite_bead_,_120_Ohm@3A_1: CLABCONF0: DNP
JP1 JP4 JP5 JP10 = Jumper,_black,_100mil: CLABCONF0: = SB-UCM
P7 = Conn.,_Micro-USB,_B-Type: CLABCONF0: = SB-UCM; P/N: 180K00501S
P8 = microSD_push-pull_1: CLABCONF0: = SB-UCM; P/N: 182K00803S
P23 = 1x4_HDR,TH_0: CLABCONF0: = SB-UCM; P/N: 190C00400
Q6 Q7 Q17-Q19 Q26 Q30 = P-MOS,_1.5A,_8V: CLABCONF0: = SB-UCM
Q22 Q23 = N-MOSFET,NDS335N,100mOhm@2.5V: CLABCONF0: = SB-UCM
R6 = 1K,1%,0402,1_16W: CLABCONF0: = SB-UCM; Group: CAN
R8 R9 = 100K,_0402: CLABCONF0: = SB-UCM; P/N: 161C10031S
R19 = 10K,1%,0402,1_16W_4: CLABCONF0: = SB-UCM
R116 R216 R244 = 0R,_0402_2: CLABCONF0: = SB-UCM
R42 R117 R222 = 0R,_0402_13: CLABCONF0: DNP
R120 R205 = 0R,_0402_10: CLABCONF0: DNP
R12 R130 = 10K,1%,0402,1_16W_5: CLABCONF0: = SB-UCM
R22 R131 R132 = 10K,1%,0402,1_16W_1: CLABCONF0: = SB-UCM
R13 R133 R272 = 10K,1%,0402,1_16W_2: CLABCONF0: = SB-UCM
R127 R134 R275 = 10K,1%,0402,1_16W: CLABCONF0: = SB-UCM
R38 R135 R300 = 10K,1%,0402,1_16W_3: CLABCONF0: = SB-UCM
R149 R192 = 0R,_0402_7: CLABCONF0: = SB-UCM
R193 R202 = 0R,_0402_9: CLABCONF0: = SB-UCM
R194 R223 = 0R,_0402: CLABCONF0: = SB-UCM
R195 = 0R,_0402_4: CLABCONF0: = SB-UCM
R196 = 0R,_0402_6: CLABCONF0: = SB-UCM
R197 = 0R,_0402_12: CLABCONF0: = SB-UCM
R66 R158 R204 R224 = 0R,_0402_5: CLABCONF0: DNP
R148 R207 R215 = 0R,_0402_1: CLABCONF0: = SB-UCM
R208 R348 = 0R,_0402_11: CLABCONF0: DNP
R201 R209 = 0R,_0402_8: CLABCONF0: = SB-UCM
R218 = 4.99K,1%,0402,1_16W: CLABCONF0: = SB-UCM; P/N: 161C25511S
R220 = 47K,_0402: CLABCONF0: = SB-UCM; P/N: 161C68001S
R287 = 120R_1%,_0603: CLABCONF0: = SB-UCM
R328 = 0R,_0402_3: CLABCONF0: = SB-UCM
RN4 = RN,8.2K,10P8R@1206: CLABCONF0: DNP
S1-S4 = MISC_SHORT_NL: CLABCONF0: DNP
SW1-SW3 = TACT_SW_6x6mm_SMT: CLABCONF0: = SB-UCM
U4 = CP2104_0: CLABCONF0: = SB-UCM; P/N: 116A00140S
U5 U9 U10 U17 = IP4220CZ6_0: CLABCONF0: = SB-UCM
U34 = AduM1201: CLABCONF0: = SB-UCM; Group: CAN
U35 = TJA1050T: CLABCONF0: = SB-UCM; Group: CAN
C47 = 100nF,_10V,_X7R,_10%,_0402_7: CLABCONF0: = SB-UCM
C51 = 22uF,6.3V,X5R_1: CLABCONF0: DNP; P/N: 151B22610S
C55 C158 = 100nF,_10V,_X7R,_10%,_0402_9: CLABCONF0: = SB-UCM
C56 C156 C305 = 100nF,_10V,_X7R,_10%,_0402_6: CLABCONF0: = SB-UCM
C57 C146 = 100nF,_10V,_X7R,_10%,_0402_5: CLABCONF0: = SB-UCM
C58 C155 = 100nF,_10V,_X7R,_10%,_0402_4: CLABCONF0: = SB-UCM
C39 C61 C302 = 100nF,_10V,_X7R,_10%,_0402_10: CLABCONF0: = SB-UCM
C62 = 22uF,6.3V,X5R_2: CLABCONF0: DNP; P/N: 151B22610S
C63 = 100nF,_10V,_X7R,_10%,_0402_3: CLABCONF0: = SB-UCM; Group: LAN2
C147 C199 = 100nF,_10V,_X7R,_10%,_0402_8: CLABCONF0: = SB-UCM
C278 = 1uF,X5R,6.3V,0402: CLABCONF0: = SB-UCM; P/N: 151D10510S
D2 D4 = BAT54WS_0: CLABCONF0: = SB-UCM
D3 = ZENER_24V_500mW_SOD-123: CLABCONF0: DNP
E5 = HDR_1x3_100MIL_TH_JUMPER: CLABCONF0: = SB-UCM
F3 F7-F9 = Fuse,_0.75A_Ih,_1.5A_It: CLABCONF0: = SB-UCM
J5 = HDMI_Connector: CLABCONF0: = SB-UCM
L8 = IND,47uH,220mA,IND1812_2: CLABCONF0: = SB-UCM; P/N: 147A22000S
L2 L5-L7 L9-L12 L26 L28 L30 = ESD_CHOKE_DIFFx2_10: CLABCONF0: = SB-UCM; P/N: 142D11801S
P10 = FPC_40_05mm: CLABCONF0: = SB-UCM; Group: Always
P11 = HDR_2x12_100MIL: CLABCONF0: = SB-UCM
Q9 Q10 = MOSFET_N_DUAL_0_0.4A_20V: CLABCONF0: = SB-UCM
R23 R151 = 0R,_0402_15: CLABCONF0: = SB-UCM
R24 = 2.2R,5%,0402,1_16W: CLABCONF0: = SB-UCM; P/N: 161C00005S
R25 = 2.2R,5%,0402,1_16W_1: CLABCONF0: = SB-UCM; P/N: 161C06R25S
R26 = 255R_1%,0402_1: CLABCONF0: = SB-UCM
R27 = 255R_1%,0402: CLABCONF0: = SB-UCM
R28 = 1K,1%,0402,1_16W_1: CLABCONF0: DNP
R29 = 1K,1%,0402,1_16W_2: CLABCONF0: DNP
R30 = 1K,1%,0402,1_16W: CLABCONF0: DNP
R156 = 0R,_0402_17: CLABCONF0: DNP
R157 = 0R,_0402_19: CLABCONF0: DNP
R199 R226 R313 = 0R,_0402_3: CLABCONF0: DNP
R142 R200 = 0R,_0402: CLABCONF0: DNP
R206 = 10K,1%,0402,1_16W_2: CLABCONF0: DNP
R141 R144 R210 = 0R,_0402_4: CLABCONF0: DNP
R211 = 0R,_0402_11: CLABCONF0: = SB-UCM
R67 R212 = 0R,_0402_12: CLABCONF0: DNP
R213 R320 = 0R,_0402_14: CLABCONF0: = SB-UCM
R214 = 0R,_0402_18: CLABCONF0: DNP
R217 = 0R,_0402_7: CLABCONF0: DNP
R219 R225 R314 = 0R,_0402_6: CLABCONF0: DNP
R221 = 0R,_0402_16: CLABCONF0: = SB-UCM
RN8 = RN,33R,8P4R@0805: CLABCONF0: = SB-UCM
RN9 RN11 RN12 RN16 = RN,10K,8P4R@0805: CLABCONF0: = SB-UCM
RN10 = RN,1K,8P4R@0805: CLABCONF0: = SB-UCM; P/N: 163K04222S
RN13 = RN,10K,8P4R@0805: CLABCONF0: DNP
RN14 = RN,0R,8P4R@0805: CLABCONF0: = SB-UCM
U14 = AIC1647_0: CLABCONF0: = SB-UCM; P/N: 123C40000S
U15 = tfp513_0: CLABCONF0: = SB-UCM; P/N: 116A01640S
U36 = 7SZ07D,_buffer: CLABCONF0: = SB-UCM; P/N: 106D20070S
C38 = 220pF,50V,NPO,0603: CLABCONF0: = SB-UCM
C148 C306 = 100nF,_10V,_X7R,_10%,_0402_12: CLABCONF0: = SB-UCM
C149 = 100nF,_10V,_X7R,_10%,_0402_14: CLABCONF0: = SB-UCM
C150 = 10nF,_25V,_X7R,_10%,_0402: CLABCONF0: DNP
C151 = 1uF,X5R,6.3V,0402: CLABCONF0: DNP
C159 C369 = 100nF,_10V,_X7R,_10%,_0402_13: CLABCONF0: = SB-UCM
C160 = 100nF,_10V,_X7R,_10%,_0402_15: CLABCONF0: = SB-UCM
C161 = 100nF,_10V,_X7R,_10%,_0402_16: CLABCONF0: = SB-UCM
C178-C180 = 10uF,6_0.3V,0603,20%X5R: CLABCONF0: = SB-UCM
C195 = 100nF,_10V,_X7R,_10%,_0402_11: CLABCONF0: = SB-UCM
C364 = 100nF,_10V,_X7R,_10%,_0402_7: CLABCONF0: DNP
F1 = Fuse,_0.75A_Ih,_1.5A_It: CLABCONF0: = SB-UCM; P/N: 175P22200S
H13 = Hole,_Plated,_M2,_5mm._ext.: CLABCONF0: DNP
J1-J3 = AUDIO_JACK_3.5mm,_no_sw.,_SMT: CLABCONF0: = SB-UCM
P3 = Conn.,_Micro-USB,_B-Type: CLABCONF0: = SB-UCM; P/N: 180K00502S
P6 = USB_A-TYPE_DOUBLE_TH: CLABCONF0: = SB-UCM; Group: Front Panel
P13 = uSIM_SOCKET_0: CLABCONF0: = SB-UCM
P16 = mini_PCIe_0: CLABCONF0: = SB-UCM; P/N: 182K05202S
Q28 = N-MOSFET,NDS335N,100mOhm@2.5V: CLABCONF0: DNP
R18 = 47K,_0402_1: CLABCONF0: = SB-UCM; P/N: 161C68001S
R20 R324 = 10K,1%,0402,1_16W_8: CLABCONF0: = SB-UCM
R21 = 47K,_0402: CLABCONF0: = SB-UCM
R37 = 10K,1%,0402,1_16W_5: CLABCONF0: DNP
R57 = 20K_1%,_0402: CLABCONF0: = SB-UCM; Group: AUD
R59 = 0.005R,2W,RCS1458: CLABCONF0: = SB-UCM; P/N: 161HR0181S
R79 = 1K,1%,0402,1_16W: CLABCONF0: = SB-UCM
R118 = 30.1R,1%,0402_1: CLABCONF0: DNP
R119 = 30.1R,1%,0402: CLABCONF0: DNP
R265 = 10K,1%,0402,1_16W_9: CLABCONF0: = SB-UCM
R267 R302 = 10K,1%,0402,1_16W_4: CLABCONF0: DNP
R268 R303 = 10K,1%,0402,1_16W_6: CLABCONF0: DNP
R269 = 10K,1%,0402,1_16W_7: CLABCONF0: DNP
R276 = 49.9R_1%,_0402_1: CLABCONF0: = SB-UCM
R277 = 49.9R_1%,_0402: CLABCONF0: = SB-UCM
R278 = 0R,_0402_1: CLABCONF0: DNP
RN19 = RN,10K,8P4R@0805: CLABCONF0: = SB-UCM; P/N: 163K04104S
SP11 SP12 = SMT_SPACER_M2x3: CLABCONF0: = SB-UCM
TP1-TP3 = TESTPOINT: CLABCONF0: DNP
U1 = TMP_0: CLABCONF0: = SB-UCM
U2 = TMP_164704: CLABCONF0: = SB-UCM
U8 = 24C02,_serial_EE,_2KB,_I2C: CLABCONF0: = SB-UCM; P/N: 111S31000S
U24 = DS2786_,Fuel_Gauge: CLABCONF0: = SB-UCM
U27 = SQPCIE100: CLABCONF0: DNP; P/N: 141C10600I
C22 = 10uF,6.3V,0603,X5R: CLABCONF0: = SB-UCM
C73 = Cap.,10uF,6.3V,0603,X5R: CLABCONF0: = SB-UCM
C74 = 100nF,_10V,_X7R,_10%,_0402_5: CLABCONF0: = SB-UCM; Group: LAN2
C79 = 100nF,_10V,_X7R,_10%,_0402_7: CLABCONF0: = SB-UCM; Group: LAN2
C181 = 100nF,_10V,_X7R,_10%,_0402_11: CLABCONF0: = SB-UCM; Group: LAN2
C182 = 100nF,_10V,_X7R,_10%,_0402: CLABCONF0: = SB-UCM; Group: LAN2
C183 = 100nF,_10V,_X7R,_10%,_0402_2: CLABCONF0: = SB-UCM; Group: LAN2
C184 = 100nF,_10V,_X7R,_10%,_0402_4: CLABCONF0: = SB-UCM; Group: LAN2
C204 = 470pF,_50V,_X7R,_10%,_0603_1: CLABCONF0: DNP
C205 = 470pF,_50V,_X7R,_10%,_0603: CLABCONF0: DNP
C303 = 100nF,_10V,_X7R,_10%,_0402_9: CLABCONF0: DNP
C304 = 100nF,_10V,_X7R,_10%,_0402_8: CLABCONF0: DNP
D10 = BAT54C: CLABCONF0: = SB-UCM
L1 = Ferrit_330R@100Mhz,0.2A: CLABCONF0: DNP; P/N: 147D22100S
OSC1 = Osc.,_50Mhz,50PPM,_3.3V: CLABCONF0: DNP; P/N: 141C25601S
P4 P5 P18 = HDR_2x17_100MIL_SMT: CLABCONF0: = SB-UCM
P21 = Con_0.,1GBit_RJ45,_short: CLABCONF0: = SB-UCM
P66 = Conn_2x12_B2B_P_0.4mm_Socket: CLABCONF0: = SB-UCM; P/N: 182K02401S
R7 = 10K,1%,0402,1_16W_7: CLABCONF0: = SB-UCM
R11 = 10K,1%,0402,1_16W_1: CLABCONF0: DNP
R69 = 0R,_0402_18: CLABCONF0: = SB-UCM
R71 = 475R_1%,_0402_1: CLABCONF0: = SB-UCM
R72 = 475R_1%,_0402: CLABCONF0: = SB-UCM
R143 = 0R,_0402_19: CLABCONF0: = SB-UCM
R145 = 0R,_0402_10: CLABCONF0: = SB-UCM
R147 = 0R,_0402_17: CLABCONF0: = SB-UCM
R150 = 0R,_0402_20: CLABCONF0: DNP
R238 = 2.2K,5%,0402.1_16W_1: CLABCONF0: DNP
R239 = 2.2K,5%,0402.1_16W: CLABCONF0: DNP
R308 = 10K,1%,0402,1_16W: CLABCONF0: DNP
R316 = Res.,_8.06K,_1%,_0402,_1_16W: CLABCONF0: = SB-UCM
R317 = 0R,_0402_9: CLABCONF0: DNP
R318 = 0R,_0402_2: CLABCONF0: DNP
R319 = 0R,_0402_8: CLABCONF0: DNP
R353 = 0R,_0402_16: CLABCONF0: DNP
U6 = TXS0102_0: CLABCONF0: = SB-UCM; P/N: 116A01020S

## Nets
AGND: C38.1 J1.1(COM) J2.1(COM) J3.1(COM) R21.2 R244.2
GND: C22.1 C24.2 C25.2 C26.2 C28.2 C29.2 C30.1 C39.1 C40.2 C41.2 C42.2 C43.2 C44.2 C45.2 C46.2 C47.2 C50.2 C51.2 C54.2 C55.1 C56.1 C57.1 C58.1 C59.1 C60.1 C61.1 C62.2 C63.2 C73.2 C74.2 C79.1 C144.2 C145.2 C146.2 C147.2 C148.2 C149.2 C150.2 C151.2 C154.2 C155.2 C156.2 C158.2 C159.2 C160.2 C161.2 C162.2 C178.2 C179.1 C180.1 C181.1 C182.1 C183.1 C184.1 C187.2 C188.2 C195.2 C196.1 C198.2 C199.2 C204.2 C205.2 C278.2 C300.2 C301.2 C302.1 C303.2 C304.2 C305.2 C306.1 C363.2 C364.1 C369.2 FB1.1 FB2.1 FB5.1 J5.2(D2_Shield) J5.5(D1_Shield) J5.8(D0_Shield) J5.11(CK_Shield) J5.17(GND) L2.5(GND) L2.6(GND) L5.5(GND) L5.6(GND) L6.5(GND) L6.6(GND) L7.5(GND) L7.6(GND) L9.5(GND) L9.6(GND) L10.5(GND) L10.6(GND) L11.5(GND) L11.6(GND) L12.5(GND) L12.6(GND) L26.5(GND) L26.6(GND) L28.5(GND) L28.6(GND) L30.5(GND) L30.6(GND) OSC1.2(GND) P5.25 P5.33 P8.6(VSS) P8.10(M1) P8.11(M2) P8.12(M3) P8.13(M4) P10.3 P10.29 P10.36 P11.5 P11.6 P11.9 P11.10 P11.13 P11.14 P11.17 P11.18 P11.21 P11.22 P13.5(GND) P13.9(M9) P13.10(M10) P13.11(M11) P13.12(M12) P16.4(GND7) P16.9(GND1) P16.15(GND2) P16.18(GND8) P16.21(GND3) P16.26(GND9) P16.27(GND4) P16.29(GND5) P16.34(GND10) P16.35(GND6) P16.37(RSVD5) P16.40(GND11) P16.50(GND12) P18.33 P18.34 P66.2(AGND) P66.15(DGND) P66.24(AF_GND) Q10.1(S1) Q10.4(S2) Q22.2(S) Q23.2(S) Q28.2(S) R11.1 R22.1 R24.2 R30.2 R38.1 R59.1 R71.2 R72.2 R116.2 R204.1 R206.1 R208.1 R210.1 R212.1 R214.1 R217.1 R226.1 R244.1 R265.1 R268.1 R272.2 R275.1 R276.2 R277.2 R278.2 R300.2 R303.1 R308.1 R324.1 R328.1 RN9.5(RD2) RN9.6(RC2) RN9.7(RB2) RN9.8(RA2) RN11.6(RC2) RN12.3(RC1) RN12.4(RD1) RN13.1(RA1) RN13.2(RB1) RN13.4(RD1) RN16.1(RA1) RN16.2(RB1) RN19.3(RC1) RN19.4(RD1) S1.1 S2.1 S4.1 SW1.1 SW1.3 SW2.1 SW2.3 U1.6(GND) U2.6(GND) U4.2(GND) U5.2(GND) U6.2(GND) U8.4(GND) U9.2(GND) U10.2(GND) U14.2(GND) U15.16(DGND) U15.17(PGND) U15.20(TGND) U15.26(TGND) U15.32(TGND) U15.34(RSVD2) U15.48(DGND) U15.56(IDCK-) U15.64(DGND) U17.2(GND) U24.5(SNS) U27.3(GND) U34.4(GND1) U36.3(GND) ; also on sheet 7 8
VBAT: U24.9(VIN) ; also on sheet 7
VBUS0: F1.2 U1.8(OUT_A) ; also on sheet 7 8
VBUS0_EN_3V3: Q28.3(D) R79.2 R141.1 RN19.5(RD2) U1.1(EN_A)
VBUS0_FUSED: C178.1 F1.1 P3.1(VBUS)
VBUS0_nOVC_OD: RN19.7(RB2) U1.2(FLG_A)
VBUS_EN_REQ: RN19.6(RC2) U2.1(EN_A) U2.4(EN_B) ; also on sheet 8
VBUS_nOVERCURRENT: RN19.8(RA2) U2.2(FLG_A) U2.3(FLG_B) ; also on sheet 8
VBUSBOTTOM: F7.1 U2.8(OUT_A)
VBUSHDR: C22.2 F3.1 P5.27
VBUSTOP: F9.1 U2.5(OUT_B)
VCC_3V3_BCKL: C50.1 C51.1 L8.1 Q18.3(D) U14.6(IN)
VCC_3V3_BCKL_DIS: Q18.1(G) R212.2 R213.2
VCC_3V3_CAN: C363.1 Q6.3(D) R9.1 U34.1(VCC1)
VCC_3V3_CAN_DIS: Q6.1(G) R204.2 R207.2
VCC_3V3_DVI: C54.1 C55.2 C56.2 C57.2 C58.2 C59.2 C60.2 C61.2 C199.1 Q9.2(G1) Q9.5(G2) Q19.3(D) R27.2 R28.2 R29.2 R127.1 RN10.7(RB2) RN10.8(RA2) RN11.5(RD2) RN11.7(RB2) RN11.8(RA2) RN12.1(RA1) RN12.2(RB1) RN13.3(RC1) RN14.8(RA2) U15.1(DVDD) U15.3(VREF) U15.12(DVDD) U15.18(PVDD) U15.23(TVDD) U15.29(TVDD) U15.33(DVDD) U15.49(N~{C}AVDD) U36.5(VCC)
VCC_3V3_DVI_DIS: Q19.1(G) R214.2 R215.2
VCC_3V3_nDC: R211.1 R213.1 R215.1
VCC_5V0_DVI: C62.1 C63.1 F8.2 Q26.3(D)
VCC_5V0_DVI_DIS: Q26.1(G) R216.2 R217.2
VCC_5V0_USB: C196.2 Q30.3(D) U2.7(VCC)
VCC_5V0_USB_DIS: Q30.1(G) R223.2 R226.2
VCC_5V_AW: C181.2 C182.2 C187.1 C195.1 E5.3 F3.2 P18.1 Q7.2(S) Q26.2(S) Q30.2(S) U1.7(VCC) ; also on sheet 7 8
VCC_5V_CAN: D19.2(ANODE) Q7.3(D)
VCC_5V_CAN_DIS: Q7.1(G) R208.2 R209.2
VCC_USB_1: C180.2 F7.2 P6.1(VBUS)
VCC_USB_2: C179.2 F9.2 P6.5(VBUS)
VCCB_MIPIHDR: E5.2 P11.1
VDD3A_ETH: L1.1 ; also on sheet 8
100MIL_CONSOLE_RX: P5.21 R133.2
100MIL_CONSOLE_TX: P5.23 R131.2
100MIL_MFUNC_PCAM_DAT0/100DIFF_5N: P18.3 R67.2
100MIL_MFUNC_PCAM_DAT1/100DIFF_5P: P18.4 R66.1
100MIL_MFUNC_PCAM_DATA_EN: P18.28 R42.1
ALT_BOOT: E1.2 Q22.1(G) SW3.2 SW3.4 ; also on sheet 8
ALT_BOOT_ACT: E1.1 R120.1 R218.1 SW3.1 SW3.3
ALTBOOT_LEDAN: DS12.ANODE R220.1
ALTBOOT_LEDCAT: DS12.CATHODE Q22.3(D)
AMPR: C37.2 R20.1
AUDBYP_SoC_GPIO1_IO01: P5.34 ; also on sheet 8
BAT_GND: R57.1 R59.2 U24.6(VSS) U24.11(PAD) ; also on sheet 7
BCKLIGHT_FB: D3.2(ANODE) R23.2 U14.3(FB)
BOOST_5V: R209.1 R216.1 R223.1 ; also on sheet 7
BQ_VBUSRC: R267.1 ; also on sheet 7
BSEL: RN13.6(RC2) RN14.3(RC1) U15.15(BSEL/SCL)
BTBYP_SoC_SAI2_RXD: P4.5 ; also on sheet 8
BTBYP_SoC_SAI2_TXC: P4.27 ; also on sheet 8
BTBYP_SoC_SAI2_TXD: P4.25 ; also on sheet 8
BTBYP_SoC_SAI2_TXFS: P4.7 ; also on sheet 8
BTBYP_SoC_UART3_CTS: P5.10 ; also on sheet 8
BTBYP_SoC_UART3_RTSorRX: P4.29 ; also on sheet 8
CAM_SCCB_EN: C26.1 R7.2 U6.6(OE)
CAN_GND: P23.4 R6.1 R328.2 U34.5(GND2) U35.2(GND)
CAN_H: P23.2 R287.1 U35.6(CANL)
CAN_L: E10.2 P23.3 U35.7(CANH)
CAN_RX_3V3: R143.1 R144.1 U34.2(OUTA)
CAN_STB_PD: R6.2 U35.8(S)
CAN_TERM: E10.1 R287.2
CAN_TX_3V3: R9.2 R142.1 R145.1 U34.3(INB)
CAN_VCC: D19.1(CATHODE) P23.1 U34.8(VCC2) U35.3(VCC)
CARRER_I2C_SDA_1V8: P66.3(SDA) R238.1 U6.5(A1)
CARRIER_EEPROM_WP: E4.1 R22.2 U8.7(WP)
CARRIER_I2C_SCL_1V8: P66.5(SCL) R239.1 U6.4(A2)
CHASSIS: H13.1 J5.20(SHELL1) J5.21(SHELL2) P3.6(SHIELD1) P3.7(SHIELD2) P3.8(SHIELD3) P3.9(SHIELD4) P6.9(SHIELD) P6.10(SHIELD) P6.11(SHIELD) P6.12(SHIELD) P7.6(SHIELD1) P7.7(SHIELD2) P7.8(SHIELD3) P7.9(SHIELD4) P21.S1(SHIELD) P21.S2(SHIELD) SP11.1 SP12.1 ; also on sheet 8
CHDET_5V: Q28.1(G) R267.2 R268.2 R269.2
COLD_RESET_IN: SW2.2 SW2.4 ; also on sheet 8
CONN_CAM_CLK: P66.13(XCLK) R300.1 R317.2 R320.2
CP2104VPP: C29.1 U4.16(VPP)
CSTRB: P66.1(STROBE) R302.2 R303.2 R318.1
D0M: L11.3 U15.24(TXD0-)
D0P: L11.4 U15.25(TXD0+)
D1M: L10.3 U15.27(TXD1-)
D1P: L10.4 U15.28(TXD1+)
D2M: L9.3 U15.30(TXD2-)
D2P: L9.4 U15.31(TXD2+)
DCLKM: L12.3 U15.21(TXC-)
DCLKP: L12.4 U15.22(TXC+)
DESKEW_LSB: R30.1 RN12.7(RB2) U15.8(DK1)
DESKEW_MIDDLE_BIT: R28.1 RN12.5(RD2) U15.7(DK2)
DESKEW_MSB: R29.1 RN12.6(RC2) U15.6(DK3)
DS2786_VPROG: R57.2 U24.7(VPROG)
DSEL: RN13.7(RB2) RN14.2(RB1) U15.14(DSEL/SDA)
DVI_5V: D4.CATHODE J5.18(+5V) RN10.5(RD2) RN10.6(RC2) U17.5(VBUS)
DVI_5V_D: D4.ANODE F8.1
DVI_DDC_SCL_5V: J5.15(DDC_CLK) Q9.6(D1) RN10.3(RC1) U17.6(IO4)
DVI_DDC_SDA_5V: J5.16(DDC_DATA) Q9.3(D2) RN10.4(RD1) U17.4(IO3)
DVI_DESKEW_ENABLE: R127.2 R206.2 U15.35(DKEN)
DVI_EN_3V3: R148.1 R156.2 RN9.1(RA1) U15.10(~{PD})
DVI_FS_ADJ: R26.1 U15.19(TFADJ)
DVI_HOTPLUG: J5.19(HP_DET) Q10.2(G1) RN11.3(RC1) U17.1(IO1)
DVI_HTPLG3V3: Q10.3(D2) R221.2 R222.1 RN11.2(RB1)
DVI_MONITOR_DET_VPER: R219.1 R221.1 RN11.4(RD1) U36.2(IN)
DVI_nHOTPLUG: Q10.5(G2) Q10.6(D1) RN11.1(RA1)
DVI_PCLK: RN8.7(RB2) U15.57(IDCK+)
DVI_TXD0N: J5.9(D0-) L11.2
DVI_TXD0P: J5.7(D0+) L11.1
DVI_TXD1N: J5.6(D1-) L10.2
DVI_TXD1P: J5.4(D1+) L10.1
DVI_TXD2N: J5.3(D2-) L9.2
DVI_TXD2P: J5.1(D2+) L9.1
DVI_TXDCN: J5.12(CK-) L12.2
DVI_TXDCP: J5.10(CK+) L12.1
EN_B: R272.1 U1.4(EN_B)
EPR_A0: R224.2 RN16.8(RA2) U8.1(A0)
EPR_A1: R225.2 RN16.7(RB2) U8.2(A1)
EPR_A2: R278.1 RN16.6(RC2) U8.3(A2)
ETH1_CT1: C73.1 C74.1 L1.2 P21.P5(CT)
ETH1_CT2: C79.2 P21.P6(CT)
ETH1_GREEN_LED_AN: C205.1 D10.3(CATHODE) P21.P12(LED1_A)
ETH1_GREEN_LED_CAT: P21.P11(LED1_C) R72.1
ETH1_LED_ACT/PHY1ADDRESS2: R69.2 ; also on sheet 8
ETH1_LINK-LED_10_100: D10.1(ANODE1) ; also on sheet 8
ETH1_LINK-LED_1000/INTSELECT: D10.2(ANODE2) ; also on sheet 8
ETH1_MDI0N: P21.P2(MDI0-) ; also on sheet 8
ETH1_MDI0P: P21.P1(MDI0+) ; also on sheet 8
ETH1_MDI1N: P21.P4(MDI1-) ; also on sheet 8
ETH1_MDI1P: P21.P3(MDI1+) ; also on sheet 8
ETH1_MDI2N: P21.P8(MDI2-) ; also on sheet 8
ETH1_MDI2P: P21.P7(MDI2+) ; also on sheet 8
ETH1_MDI3N: P21.P10(MDI3-) ; also on sheet 8
ETH1_MDI3P: P21.P9(MDI3+) ; also on sheet 8
ETH1_YELLOW_LED_AN: C204.1 P21.P14(LED2_A) R69.1
ETH1_YELLOW_LED_CAT: P21.P13(LED2_C) R71.1
ETH1BYP_SoC_ENET1_TD2: P4.22 ; also on sheet 8
ETHBYP_SoC_SD2_CD_B/ALT5_GPIO5_9/SBC_CAM_WEN: P18.30 R42.2 ; also on sheet 8
ETHBYP_SoC_SD2_WP: P4.12 ; also on sheet 8
F_S_ADJ: R26.2 R27.1
FLASH_nWP: R116.1 R117.1 ; also on sheet 8
HSUSB_GND: FB2.2 P6.4(GND) P6.8(GND) S2.2
ISEL: RN13.8(RA2) RN14.1(RA1) U15.13(ISEL/~{RESET})
LCD_nSTANDBY_3V3: P10.31 R149.1 R158.2 RN9.4(RD1)
LCD_PCLK: P10.30 RN8.6(RC2)
LHPOUT: J1.2(L) ; also on sheet 8
LLINEIN: J3.2(L) ; also on sheet 8
LVDS_EN_3V3: R205.2 RN9.3(RC1)
MCLK_VCC: C304.1 OSC1.4(VCC) R348.2 R353.2
MIC_IN: C37.1 C38.2 J2.2(L) R18.2 R21.1
MICBIAS: R18.1 ; also on sheet 8
MICIN: R20.2 ; also on sheet 8
MIPI_CAM_MCLK: R316.2 R320.1
MIPI_DSI_CLK_N: L26.3 P11.8
MIPI_DSI_CLK_P: L26.4 P11.7
MIPI_DSI_D0_N: L30.3 P11.20
MIPI_DSI_D0_P: L30.4 P11.19
MIPI_DSI_D1_N: L28.3 P11.4
MIPI_DSI_D1_P: L28.4 P11.3
MIPI_DSI_DDC_SCL: P11.23 R199.1 R202.1
MIPI_DSI_DDC_SDA: P11.24 R200.2 R201.2
MIPICAM_DVDD1V5: C303.1 P66.10(DVDD1.5V) R313.1
MIPICAM_PWDN: P66.8(PWDN) Q23.3(D) R11.2 R12.1 R150.1
MIPICAM_RESETB: P66.6(RESET) R13.1 R324.2
MIPICAM_STROBE: P5.28 R318.2
mPCIE0_LED1: P16.42(LED_WWAN#) TP1.1
mPCIE0_LED2: P16.44(LED_WLAN#) TP2.1
mPCIE0_LED3: P16.46(LED_WPAN#) TP3.1
mPCIE_USB_DN: L5.4 P16.36(USB_D-)
mPCIE_USB_DP: L5.3 P16.38(USB_D+)
OSC25MHZ: OSC1.3(OUT) R317.1
OSCEN: OSC1.1(EN) R308.2 R314.1 R319.1
OTG_DN: L2.2 P3.2(D-)
OTG_DP: L2.1 P3.3(D+)
PCIE0_nPERST_3V3: P16.22(PERST#) R37.1 R38.2 R147.1
PCIE_REFCLK_CLKN_OSC: R119.1 U27.5(\\~{OU}T)
PCIE_REFCLK_CLKP_OSC: R118.1 U27.4(OUT)
PMIC_STBY_REQ: P5.32 ; also on sheet 8
PMIDU: R269.1 ; also on sheet 7
PWDN_CAM_DLY: C30.2 Q23.1(G) R8.2
RHPOUT: J1.3(R) ; also on sheet 8
RLINEIN: J3.3(R) ; also on sheet 8
RXD_OUTB: U34.6(OUTB) U35.1(TxD)
SB_PWR_EN_REQ: R151.1 ; also on sheet 8
SDCARD_CLK: P8.5(CLK) R196.1 RN4.7(R6) U10.4(IO3)
SDCARD_CMD: P8.3(CMD) R197.1 RN4.8(R7) U10.6(IO4)
SDCARD_DAT0: P8.7(DAT0) R195.1 RN4.4(R4) U9.6(IO4)
SDCARD_DAT1: P8.8(DAT1) R194.1 RN4.3(R3) U9.4(IO3)
SDCARD_DAT2: P8.1(DAT2) R193.1 RN4.2(R2) U9.3(IO2)
SDCARD_DAT3: P8.2(DAT3) R192.1 RN4.1(R1) U9.1(IO1)
SERIAL_USBGND: FB5.2 P7.5(GND) S4.2
SERIAL_VBUS: C28.1 FB4.1 S3.1 U4.7(REGIN) U4.8(VBUS) U5.4(IO3)
SERIAL_VBUSIN: FB4.2 P7.1(VBUS) S3.2
SIM1_CLK: P13.3(CLK) P16.12(UIM_CLK)
SIM1_IO: P13.7(IO) P16.10(UIM_DATA)
SIM1_RST: P13.2(RST) P16.14(UIM_RESET)
SIM1_VCC: P13.1(VCC) P16.8(UIM_PWR)
SIM1_VPP: P13.6(VPP) P16.16(UIM_VPP)
SoC_ECSPI2_MISO/ALT3_CSI_D8/SBC_CAM_D8: P18.11 ; also on sheet 8
SoC_ECSPI2_MOSI/ALT3_CSI_D7/SBC_CAM_D7: P18.10 ; also on sheet 8
SoC_ECSPI2_SCLK/ALT3_CSI_D6/SBC_CAM_D6: P18.9 ; also on sheet 8
SoC_ECSPI2_SS0/ALT3_CSI_D9/SBC_CAM_D9: P18.12 ; also on sheet 8
SoC_EPDC_BDR0/ALT5_GPIO2_28/SBC_DVI_MSEN: P5.18 R132.2 U36.4(OUT) ; also on sheet 8
SoC_EPDC_BDR1/ALT5_GPIO2_29/SBC_PCIe_nPERST: P4.20 R147.2 ; also on sheet 8
SoC_EPDC_D00/ALT7_LCDIF_CLK/SBC_PDISP_CLK: RN8.1(RA1) RN8.2(RB1) RN8.3(RC1) ; also on sheet 8
SoC_EPDC_D01/ALT7_LCDIF_ENABLE/SBC_PDISP_DE: P10.34 U15.2(DE) ; also on sheet 8
SoC_EPDC_D02/ALT7_LCDIF_VSYNC/SBC_PDISP_VSYNC: P10.33 U15.5(VSYNC) ; also on sheet 8
SoC_EPDC_D03/ALT7_LCDIF_HSYNC/SBC_PDISP_HSYNC: P10.32 U15.4(HSYNC) ; also on sheet 8
SoC_EPDC_D04/ALT6_LCDIF_D4/SBC_PDISP_D4: P10.25 U15.59(PD4) ; also on sheet 8
SoC_EPDC_D05/ALT6_LCDIF_D5/SBC_PDISP_D5: P10.26 U15.58(PD5) ; also on sheet 8
SoC_EPDC_D06/ALT6_LCDIF_D6/SBC_PDISP_D6: P10.27 U15.55(PD6) ; also on sheet 8
SoC_EPDC_D07/ALT6_LCDIF_D7/SBC_PDISP_D7: P10.28 U15.54(PD7) ; also on sheet 8
SoC_EPDC_D08/ALT6_LCDIF_D8/SBC_PDISP_D8: P10.13 U15.53(PD8) ; also on sheet 8
SoC_EPDC_D09/ALT6_LCDIF_D9/SBC_PDISP_D9: P10.14 U15.52(PD9) ; also on sheet 8
SoC_EPDC_D10/ALT6_LCDIF_D10/SBC_PDISP_D10: P10.15 U15.51(PD10) ; also on sheet 8
SoC_EPDC_D11/ALT6_LCDIF_D11/SBC_PDISP_D11: P10.16 U15.50(PD11) ; also on sheet 8
SoC_EPDC_D12/ALT6_LCDIF_D12/SBC_PDISP_D12: P10.17 U15.47(PD12) ; also on sheet 8
SoC_EPDC_D13/ALT6_LCDIF_D13/SBC_PDISP_D13: P10.18 U15.46(PD13) ; also on sheet 8
SoC_EPDC_D14/ALT6_LCDIF_D14/SBC_PDISP_D14: P10.19 U15.45(PD14) ; also on sheet 8
SoC_EPDC_D15/ALT6_LCDIF_D15/SBC_PDISP_D15: P10.20 U15.44(PD15) ; also on sheet 8
SoC_EPDC_PWRCOM: P4.10 R13.2 ; also on sheet 8
SoC_EPDC_PWRSTAT/ALT5_GPIO2_31/SBC_CHRGR_nIRQ: P5.13 ; also on sheet 7 8
SoC_GPIO1_2/ALT1_PWM2_OUT/SBC_LCDBCKLT_EN: R157.2 RN9.2(RB1) U14.4(EN/PWM) ; also on sheet 8
SoC_GPIO1_3/ALT0_GPIO1_3/SBC_CAM_SHUTTER: P18.24 ; also on sheet 8
SoC_GPIO1_5/ALT1_OTG1_PWR/SBC_OTG_PWREN: R79.1 ; also on sheet 7 8
SoC_GPIO1_8/ALT4_I2C3_SCL/SBC_DVI_DDC_SCL: P4.21 Q9.1(S1) R202.2 RN10.2(RB1) ; also on sheet 8
SoC_GPIO1_9/ALT4_I2C3_SDA/SBC_DVI_DDC_SDA: P4.23 Q9.4(S2) R201.1 RN10.1(RA1) ; also on sheet 8
SoC_GPIO1_10/ALT4_I2C4_SCL/SBC_CARRIER_SCL: P16.30(SMB_CLK) R199.2 RN14.6(RC2) U6.1(B2) U8.6(SCL) U24.3(SCL) ; also on sheet 7 8
SoC_GPIO1_11/ALT4_I2C4_SDA/SBC_CARRIER_SDA: P16.32(SMB_DATA) R200.1 RN14.7(RB2) U6.8(B1) U8.5(SDA) U24.4(SDA) ; also on sheet 7 8
SoC_I2C1_SCL: P4.2 R143.2 ; also on sheet 8
SoC_I2C1_SDA: P4.4 R145.2 ; also on sheet 8
SoC_I2C2_SCL: P4.6 ; also on sheet 8
SoC_I2C2_SDA: P4.18 R150.2 ; also on sheet 8
SoC_I2C3_SCL: P4.32 R144.2 ; also on sheet 8
SoC_I2C3_SDA: P4.34 R142.2 ; also on sheet 8
SoC_I2C4_SCL: P5.17 R148.2 ; also on sheet 8
SoC_I2C4_SDA: P5.15 R316.1 ; also on sheet 8
SoC_LCD1_CLK: P4.31 ; also on sheet 8
SoC_LCD1_DATA00/ALT0_LCDIF_D0/SBC_PDISP_D0/SRC_BT_CFG0: P10.21 U15.63(PD0) ; also on sheet 8
SoC_LCD1_DATA01/ALT0_LCDIF_D1/SBC_PDISP_D1/SRC_BT_CFG1: P10.22 U15.62(PD1) ; also on sheet 8
SoC_LCD1_DATA02/ALT0_LCDIF_D2/SBC_PDISP_D2/SRC_BT_CFG2: P10.23 U15.61(PD2) ; also on sheet 8
SoC_LCD1_DATA03/ALT0_LCDIF_D3/SBC_PDISP_D3/SRC_BT_CFG3: P10.24 U15.60(PD3) ; also on sheet 8
SoC_LCD1_DATA04/ALT3_CSI_VSYNC/SBC_CAM_VSYNC/SRC_BT_CFG4: P18.31 ; also on sheet 8
SoC_LCD1_DATA05/ALT3_CSI_HSYNC/SBC_CAM_HSYNC/SRC_BT_CFG5: P18.32 ; also on sheet 8
SoC_LCD1_DATA06/ALT3_CSI_PIXCLK/SBC_CAM_PCLK/SRC_BT_CFG6: P18.26 ; also on sheet 8
SoC_LCD1_DATA07/SRC_BT_CFG7: P4.8 ; also on sheet 8
SoC_LCD1_DATA08/SRC_BT_CFG8: P5.8 R151.2 ; also on sheet 8
SoC_LCD1_DATA09/SRC_BT_CFG9: P5.12 ; also on sheet 8
SoC_LCD1_DATA10/SRC_BT_CFG10: P4.14 ; also on sheet 8
SoC_LCD1_DATA11/SRC_BT_CFG11: P4.16 ; also on sheet 8
SoC_LCD1_DATA12/ALT3_CSI_D5/SBC_CAM_D5/SRC_BT_CFG12: P18.8 ; also on sheet 8
SoC_LCD1_DATA13/ALT3_CSI_D4/SBC_CAM_D4/SRC_BT_CFG13: P18.7 ; also on sheet 8
SoC_LCD1_DATA14/ALT3_CSI_D3/SBC_CAM_D3/SRC_BT_CFG14: P18.6 ; also on sheet 8
SoC_LCD1_DATA15/ALT3_CSI_D2/SBC_CAM_D2/SRC_BT_CFG15: P18.5 ; also on sheet 8
SoC_LCD1_DATA16/ALT0_LCDIF_D16/SBC_PDISP_D16/SRC_BT_CFG16: P10.5 U15.43(PD16) ; also on sheet 8
SoC_LCD1_DATA17/ALT0_LCDIF_D17/SBC_PDISP_D17/SRC_BT_CFG17: P10.6 U15.42(PD17) ; also on sheet 8
SoC_LCD1_DATA18/ALT0_LCDIF_D18/SBC_PDISP_D18/SRC_BT_CFG18: P10.7 U15.41(PD18) ; also on sheet 8
SoC_LCD1_DATA19/ALT0_LCDIF_D19/SBC_PDISP_D19/SRC_BT_CFG19: P10.8 U15.40(PD19) ; also on sheet 8
SoC_LCD1_DATA20/ALT0_LCDIF_D20/SBC_PDISP_D20: P10.9 U15.39(PD20) ; also on sheet 8
SoC_LCD1_DATA21/ALT0_LCDIF_D21/SBC_PDISP_D21: P10.10 U15.38(PD21) ; also on sheet 8
SoC_LCD1_DATA22/ALT0_LCDIF_D22/SBC_PDISP_D22: P10.11 U15.37(PD22) ; also on sheet 8
SoC_LCD1_DATA23/ALT0_LCDIF_D23/SBC_PDISP_D23: P10.12 U15.36(PD23) ; also on sheet 8
SoC_LCD1_ENABLE: P4.33 ; also on sheet 8
SoC_LCD1_HSYNC: P4.1 ; also on sheet 8
SoC_LCD1_RESET/ALT5_GPIO3_4/SBC_CAM_RESET: P18.29 ; also on sheet 8
SoC_LCD1_VSYNC: P4.3 ; also on sheet 8
SoC_MIPI_CSI_CLK_N: P66.18(MCN) ; also on sheet 8
SoC_MIPI_CSI_CLK_P: P66.16(MCP) ; also on sheet 8
SoC_MIPI_CSI_D0_N: P66.22(MDN0) ; also on sheet 8
SoC_MIPI_CSI_D0_P: P66.20(MDP0) ; also on sheet 8
SoC_MIPI_CSI_D1_N: P66.14(MDN1) ; also on sheet 8
SoC_MIPI_CSI_D1_P: P66.12(MDP1) ; also on sheet 8
SoC_MIPI_DSI_CLK_N: L26.2 ; also on sheet 8
SoC_MIPI_DSI_CLK_P: L26.1 ; also on sheet 8
SoC_MIPI_DSI_D0_N: L30.2 ; also on sheet 8
SoC_MIPI_DSI_D0_P: L30.1 ; also on sheet 8
SoC_MIPI_DSI_D1_N: L28.2 ; also on sheet 8
SoC_MIPI_DSI_D1_P: L28.1 ; also on sheet 8
SoC_ONOFF: SW1.2 SW1.4 ; also on sheet 8
SoC_PCIE_REFCLKIN_N: R67.1 R119.2 R275.2 ; also on sheet 8
SoC_PCIE_REFCLKIN_P: R66.2 R118.2 R265.2 ; also on sheet 8
SoC_PCIE_REFCLKOUT_N: P16.11(REFCLK-) R276.1 ; also on sheet 8
SoC_PCIE_REFCLKOUT_P: P16.13(REFCLK+) R277.1 ; also on sheet 8
SoC_PCIE_RX_N: P16.23(PER_N0) ; also on sheet 8
SoC_PCIE_RX_P: P16.25(PER_P0) ; also on sheet 8
SoC_PCIE_TX_N: P16.31(PET_N0) ; also on sheet 8
SoC_PCIE_TX_P: P16.33(PET_P0) ; also on sheet 8
SoC_SD1_CD_B/ALT0_SD1_CD_B/SBC_SDCARD_CD: P8.9(CD#) R19.2 ; also on sheet 8
SoC_SD1_CLK/ALT0_SD1_CLK/SBC_SDCARD_CLK: R196.2 ; also on sheet 8
SoC_SD1_CMD/ALT0_SD1_CMD/SBC_SDCARD_CMD: R197.2 ; also on sheet 8
SoC_SD1_DATA0/ALT0_SD1_D0/SBC_SDCARD_D0: R195.2 ; also on sheet 8
SoC_SD1_DATA1/ALT0_SD1_D1/SBC_SDCARD_D1: R194.2 ; also on sheet 8
SoC_SD1_DATA2/ALT0_SD1_D2/SBC_SDCARD_D2: R193.2 ; also on sheet 8
SoC_SD1_DATA3/ALT0_SD1_D3/SBC_SDCARD_D3: R192.2 ; also on sheet 8
SoC_SD1_RESET_B: P5.2 ; also on sheet 8
SoC_SD1_WP/ALT0_SD1_WP/SBC_SDCARD_WP: P5.30 R149.2 ; also on sheet 8
SoC_UART1_RXD/ALT0_UART1_RX/SBC_CONSOLE_RX: R133.1 R134.2 ; also on sheet 8
SoC_UART1_TXD/ALT0_UART1_TX/SBC_CONSOLE_TX: R131.1 R135.2 ; also on sheet 8
SoC_USB_OTG1_DN/SoC_USB_OTG_DN: L2.3 ; also on sheet 8
SoC_USB_OTG1_DP/SoC_USB_OTG_DP: L2.4 ; also on sheet 8
SoC_USB_OTG1_ID/SoC_USB_OTG_ID: P3.4(ID) ; also on sheet 8
SoC_USB_OTG2_DN/SoC_USB_HOST_DN: P5.29 ; also on sheet 8
SoC_USB_OTG2_DP/SoC_USB_HOST_DP: P5.31 ; also on sheet 8
SOM_RX: R134.1 U4.21(TXD)
SOM_TX: R135.1 U4.20(RXD)
TFP410_HTPLG: R222.2 U15.9(HTPLG)
TFP410_MSEN: R219.2 U15.11(MSEN)
TS_XN: P5.6 P10.39 ; also on sheet 8
TS_XP: P5.4 P10.37 ; also on sheet 8
TS_YN: P5.16 P10.38 ; also on sheet 8
TS_YP: P5.14 P10.40 ; also on sheet 8
TXD_INA: U34.7(INA) U35.4(RxD)
USB0_GND: FB1.2 P3.5(GND) S1.2
USB1N_C: L6.2 P6.2(D-)
USB1P_C: L6.1 P6.3(D+)
USB2N_C: L7.2 P6.6(D-)
USB2P_C: L7.1 P6.7(D+)
USBH_DN1: L6.3 ; also on sheet 8
USBH_DN2: L5.1 ; also on sheet 8
USBH_DN3: L7.3 ; also on sheet 8
USBH_DP1: L6.4 ; also on sheet 8
USBH_DP2: L5.2 ; also on sheet 8
USBH_DP3: L7.4 ; also on sheet 8
USBSERIAL_3V45: C24.1 C25.1 R130.2 U4.5(VIO) U4.6(VDD)
USBSERIAL_DN: P7.2(D-) U4.4(DN) U5.6(IO4)
USBSERIAL_DP: P7.3(D+) U4.3(DP) U5.1(IO1)
USBSERIAL_nRST: R130.1 U4.9(RST#)
VSB_1V5: C155.1 C156.1 C158.1 C159.1 C160.1 C161.1 C162.1 P16.6(+1.5V_1) P16.28(+1.5V_2) P16.48(+1.5V_3) R313.2 ; also on sheet 7
VSB_1V8: C300.1 C301.1 C302.2 C305.1 P18.25 P66.11(DVDD1.8V/2.8V) P66.23(AF-VCC2.8V) R7.1 R12.2 R238.2 R239.2 R319.2 R353.1 U6.3(VCCA) ; also on sheet 7
VSB_2V8: C306.2 P18.22 P66.4(AVDD) R8.1 R302.1 R314.2 ; also on sheet 7
VSB_3V3_AW: C40.1 C41.1 C42.1 C43.1 C44.1 C45.1 C144.1 C145.1 C146.1 C147.1 C148.1 C149.1 C150.1 C151.1 C154.1 C183.2 C184.2 C188.1 C364.2 C369.1 E4.2 E5.1 P5.5 P5.11 P8.4(VDD) P11.2 P16.2(+3.3V_1) P16.24(+3.3V_AUX) P16.39(RSVD6) P16.41(RSVD7) P16.52(+3.3V_2) P18.2 Q6.2(S) Q17.2(S) Q18.2(S) Q19.2(S) R19.1 R37.2 R117.2 R120.2 R132.1 R141.2 R156.1 R157.1 R158.1 R205.1 R220.2 R348.1 RN4.5(COM1) RN4.10(COM2) RN16.3(RC1) RN19.1(RA1) RN19.2(RB1) U6.7(VCCB) U8.8(VCC) U9.5(VBUS) U10.5(VBUS) U27.1(OE) U27.6(VCC) ; also on sheet 7 8
VSB_3V3_LCD: C46.1 C47.1 P10.4 Q17.3(D)
VSB_3V3_LCD_DIS: Q17.1(G) R210.2 R211.2
VSB_3V3_nDC: R207.1 ; also on sheet 7 8
VSYS: C198.1 R218.2 U24.10(VDD) ; also on sheet 7 8
WLANBYP_SoC_SD2_CLK: P4.19 ; also on sheet 8
WLANBYP_SoC_SD2_CMD: P4.9 ; also on sheet 8
WLANBYP_SoC_SD2_DATA0: P4.17 ; also on sheet 8
WLANBYP_SoC_SD2_DATA1: P4.15 ; also on sheet 8
WLANBYP_SoC_SD2_DATA2: P4.13 ; also on sheet 8
WLANBYP_SoC_SD2_DATA3: P4.11 ; also on sheet 8
WLD_CAT: P10.1 R23.1 R25.1
WLD_OUT: C278.1 D2.CATHODE D3.1(CATHODE) P10.2 U14.5(OVP)
WLD_RES: R24.1 R25.2
WLD_SW: D2.ANODE L8.2 U14.1(LX)
N26392546: C39.2 R224.1 R225.1

Not connected (* = marked no-connect by the designer): FID1 1*; FID2 1*; FID3 1*; FID4 1*; FID5 1*; FID6 1*; J2 3(R)*; J5 13(CE_Remote)* 14(NC)*; P4 24* 26* 28* 30*; P5 1* 3* 7* 9* 19* 20* 22* 24* 26*; P7 4(ID)*; P10 35*; P11 11* 12* 15* 16*; P13 4(RSVD4)* 8(RSVD8)*; P16 1(WAKE#)* 3(RSVD1)* 5(RSVD2)* 7(CLKREQ#)* 17(RSVD3)* 19(RSVD4)* 20(RSVD18)* 43(RSVD8)* 45(RSVD9)* 47(RSVD10)* 49(RSVD11)* 51(RSVD12)*; P18 13* 14* 15* 16* 17* 18* 19* 20* 21* 23* 27*; P66 7(NC)* 9(NC)* 17(NC)* 19(NC)* 21(NC)*; RN4 6(R5)* 9(R8)*; RN8 4(RD1)* 5(RD2)* 8(RA2)*; RN12 8(RA2)*; RN13 5(RD2)*; RN14 4(RD1)* 5(RD2)*; RN16 4(RD1)* 5(RD2)*; U1 3(FLG_B)* 5(OUT_B)*; U4 1(RI)* 10(NC)* 11(GPIO3)* 12(GPIO2)* 13(GPIO1)* 14(GPIO0)* 15(SUSPEND#)* 17(SUSPEND)* 18(CTS)* 19(RTS)* 22(DSR)* 23(DTR)* 24(DCD)*; U5 3(IO2)* 5(VBUS)*; U10 1(IO1)* 3(IO2)*; U17 3(IO2)*; U24 1(AIN1)* 2(AIN0)* 8(VOUT)*; U27 2(NC)*; U35 5(Vref)*

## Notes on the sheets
sheet 1
- MIPI-CSI MODULE
- COMPATIBLE CAMERA MODULE: LI-OV5640-MIPI-AF
- Default I2C address (SCCB slave ID): 0x78
- DNP
- DNP
- DNP
- DNP
- DNP
- DNP
- DNP
- DNP
- MCLK PROVISIONS
- up to 140mA
- DNP
- DNP
- DNP
- DNP
- DNP
- DNP
- DNP
- DNP
- SoM ETHERNET RJ45
- PARALLEL CAMERA HEADER
- DNP
- DNP
- DNP
- DNP
- NOTE: it is not clear whether DATA_EN
   is the same as WEN signal,
   so R42 is DNP by default
- PINOUT SIMILAR TO SB-FX6
- DNP
- DNP
- AUXILIARY 100MIL HEADERS
- DNP
- Place near P4
- DNP
- DNP
sheet 2
- BOARD REVISION: 1.0
sheet 3
- SB-UCM
- BOARD REVISION: 1.0
- PAGE
- DESCRIPTION
- 01
- Index
- 02
- Board Revision History
- 03
- CompuLab CoM/SoM Interface
- 04
- Debug Interface
- 05
- Parallel Display Interface
- 06
- HDMI & LVDS
- 07
- PCIE & SATA
- 08
- USB & Headers
- 09
- Camera & Ethernet
- 10
- DC Only / Main Power
- 11
- DC / USB / Battery Power
- CARRIER BOARD PRIMARY I2C BUS SLAVES (7bit address):
  ----------------------------------------------------------------
  0b010,0000 - Carrier GPIO Expander
  0b011,0110 - DS2786 Battery Supervisor
  0b011,1001 - DVI Transmitter
  0b101,0000..0b1010011 - Carrier ID EEPROM
  0b110,1011 - BQ24161 battery charger & power-path
  0b111,1000 - LI-OV5640 default slave address (sccb slave ID)
sheet 4
- PRIMARY SERIAL
  DEBUG PORT
- micro SD SLOT
  (BOOTABLE)
- DNP
- DNP
- DEBUG PORT
  (microUSB2.0 Type B)
  UART over USB
- DNP
- DNP
- DNP
- POWER/RESET/BOOT SWITCHES
- LED ON when alternate boot sequence is enabled
  LED OFF otherwise
- ALT_BOOT(pulled LOW on module):
        LOW - normal boot sequence
        HIGH - alternative boot sequence
- DNP
- module onboard EEPROM/SPI-Flash write protection feature
  (Signal pulled high onboard module):
  Low - EEPROM write-protected. SPI flash write protection allowed
  High - EEPROM & SPI-Flash writeable
- DNP
- LED ON when alternate boot sequence is enabled
  LED OFF otherwise
- Module ON/OFF button
  While module is in OFF state:
  A. short press triggers module transition to ON state.
  While module is in ON state:
  A. Short press generates interrupt (intended for SW controlled power down).
  B. Long (above ~5s) press and hold forces module immediate unconditional transition to OFF state
- module main reset button:
  press and hold for 31mS or longer to trigger module cold reset.
- CAN TRANSCEIVER
- DNP
- DNP
sheet 5
- PARALLEL
  RGB LCD
  & TOUCH
- SHENZHEN STARTEK
  ELECTRONIC TECHNOLOGY
  KD050C-1A-TP LCD
- MIPI-DSI HEADER
- DNP
- PINOUT SIMILAR TO SB-FX6/SB-T54/SB-SOM
- Place on
  board bottom
- DNP
- KD050C-1A-TP
- XR
- DNP
- YD
- XL
- YU
- DNP
- Typical LED configuration: Two parallel chains of 6 serially connected LEDs
- DNP
- DNP
- DNP
- DNP
- DNP
- DNP
- PARALLEL RGB-to-DVI
- 250mA
- DNP
- DNP
- DNP
- DNP
- DNP
- Circuitry is designed to shift
  DDC signals logic levels between
  VSB_PER (1.8 or 3.3V) and 5V.
- DNP
- DNP
- STRAPS:
   Without I2C:
     1. Monitor detection through MSEN
     2. 24bit input mode
     3. RGB data latched on rising PCLK edge
     4. De-skewing is set to 0b001 (-0.9nS <-> -0.75 nS)
   With I2C: Full SW control
- DNP
- 7-bit I2C address:
  0b011,1001
- DNP
- DNP
- Assemble for NON I2C config
- DNP
- Assemble for I2C config
sheet 6
- PRIMARY mini-PCIE + uSIM1
- DNP
- Full size Card
- PCIE REFCLK PROVISION
- DNP
- Half size Card
- ANALOG
  AUDIO
- CARRIER BOARD EEPROM
- MIC.IN
- Populate jumper to write protect
  carrier board eeprom
- DNP
- DNP
- I2C slave address: 0x54..0x57
- DNP
- AUDIO OUT
- Li-Po Battery Connector
   & Charging supervisor
- DNP
- LINE IN
- 7-bit I2C address:
  0b011,0110
- USB
- DNP
- DNP
- Circuitry makes sure we keep onboard VBUS
  load switch (U1) turned off in case SoM board
  draws its main power (VCC_CM) from
  that same VBUS rail (preventing circular
  power dependency).
- DNP
- DNP
- DNP
- DNP
- DNP
- DNP
